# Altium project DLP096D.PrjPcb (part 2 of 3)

## Sheet DLP096D_DMD_Power.SchDoc: DMD Power
size 431 x 279 mm; Date: Not shown in title block; ApprovedBy: Not shown in title block; CheckedBy: Not shown in title block; Author: Not shown in title block; CompanyName: Not shown in title block; DrawnBy: A. Whitehead; Engineer: Not shown in title block; Organization: Not shown in title block; Address1: Not shown in title block; Address2: Not shown in title block; Address3: Not shown in title block; Address4: Not shown in title block; DocumentNumber: 5; Revision: Use project parameter SCH_Rev; SheetNumber: 5; SheetTotal: 10; PageSetup: Record=PageOptions¦CenterHorizontal=True¦CenterVertical=True¦PrintScale=1.00¦XCorrection=1.00¦YCorrection=1.00¦PrintKind=0¦BorderSize=5000000¦LeftOffset=0¦BottomOffset=0¦Orientation=2¦PaperLength=1000¦PaperWidth=1000¦Scale=100¦PaperSource=15¦PrintQuality=600¦MediaType=1¦DitherType=10¦PaperKind=Letter¦PrintScaleMode=1
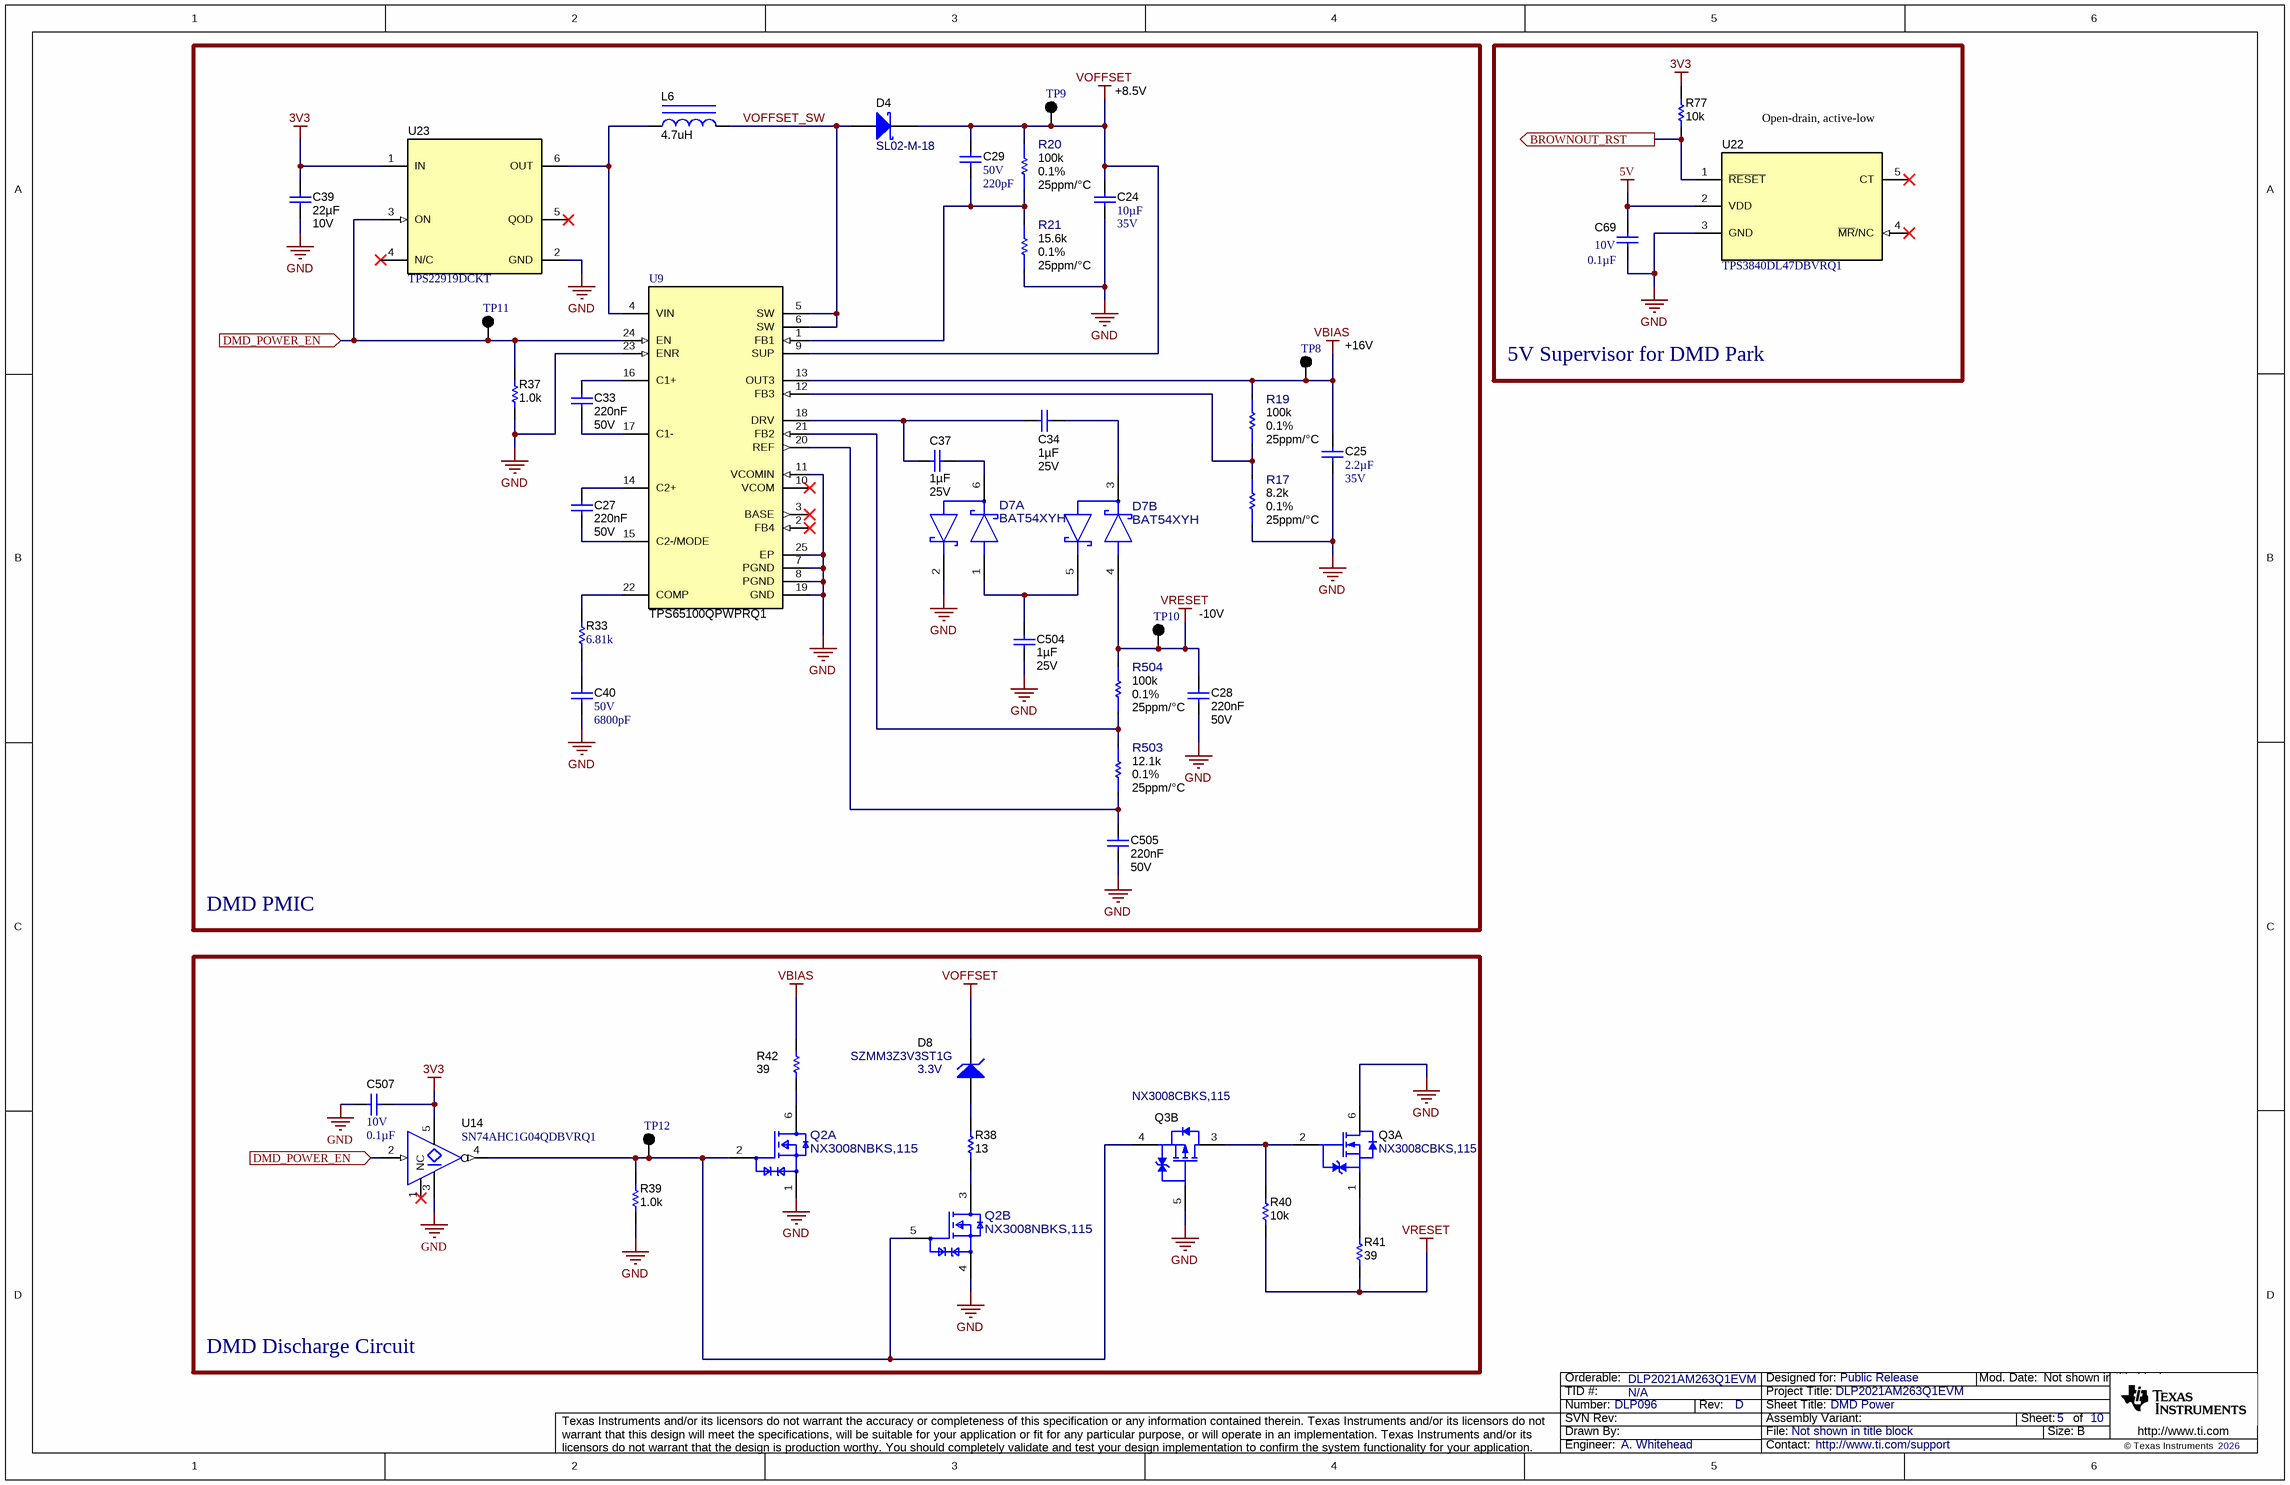
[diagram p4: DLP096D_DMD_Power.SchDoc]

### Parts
C24  Cap_F: 10µF  VDC_V: 35V  [0805_HV]  (hidden comment: C2012X5R1V106K085AC)
C25  Cap_F: 2.2µF  VDC_V: 35V  [0603]  (hidden comment: GRM188R6YA225KA12D)
C27  Cap_F: 220nF  VDC_V: 50V  [0603L]  (hidden comment: GCM188R71E104KA57D)
C28  Cap_F: 220nF  VDC_V: 50V  [0603L]  (hidden comment: GCM188R71E104KA57D)
C29  VDC_V: 50V  ValueDisplayed: 220pF  [0402]  (hidden comment: GRM155R71H221KA01D)
C33  Cap_F: 220nF  VDC_V: 50V  [0603L]  (hidden comment: GCM188R71E104KA57D)
C34  Cap_F: 1µF  VDC_V: 25V  [0603L]  (hidden comment: GCM188R71E105KA64D)
C37  Cap_F: 1µF  VDC_V: 25V  [0603L]  (hidden comment: GCM188R71E105KA64D)
C39  ValueDisplayed: 22µF  VDC_V: 10V  [1206_190L]  (hidden comment: CGA5L1X7S1A226M160AC)
C40  VDC_V: 50V  ValueDisplayed: 6800pF  [0402]  (hidden comment: CGA2B2X7R1H682K050BA)
C69  VDC_V: 10V  ValueDisplayed: 0.1µF  [0402]  (hidden comment: C0402C104K8RACTU)
C504  Cap_F: 1µF  VDC_V: 25V  [0603L]  (hidden comment: GCM188R71E105KA64D)
C505  Cap_F: 220nF  VDC_V: 50V  [0603L]  (hidden comment: CGA3E3X7R1H224K080AB)
C507  VDC_V: 10V  ValueDisplayed: 0.1µF  [0402]  (hidden comment: C0402C104K8RACTU)
D4  SL02-M-18  [DO-219AB]
D7  BAT54XYH  [FP-BAT54XYH_SOT363-IPC_C]  (parts A,B of 2)
D8  SZMM3Z3V3ST1G  value 3.3V  [SOD-323]
L6  ValueDisplayed: 4.7uH  [FDSD0420]  (hidden comment: FDSD0420D-4R7M)
Q2  NX3008NBKS,115  [FP-NX3008NBKS,115_TSSOP6-IPC_C]  (parts A,B of 2)
Q3  NX3008CBKS,115  [SOT-363]  (parts A,B of 2)
R17  Res_ohm: 8.2k  Tolerance_%: 0.1%  TempCo: 25ppm/°C  [FP-ERA-2AEB822X_0402-IPC_C]  (hidden comment: ERA-2AEB822X)
R19  TempCo: 25ppm/°C  Tolerance_%: 0.1%  Res_ohm: 100k  [FP-ERA-2AEB104X_0402-IPC_C]  (hidden comment: ERA-2AEB104X)
R20  TempCo: 25ppm/°C  Tolerance_%: 0.1%  Res_ohm: 100k  [FP-ERA-2AEB104X_0402-IPC_C]  (hidden comment: ERA-2AEB104X)
R21  Res_ohm: 15.6k  Tolerance_%: 0.1%  TempCo: 25ppm/°C  [FP-TNPW040215K6BEED_0402-IPC_C]  (hidden comment: TNPW040215K6BEED)
R33  ValueDisplayed: 6.81k  [0402]  (hidden comment: CRCW04026K81FKED)
R37  ValueDisplayed: 1.0k  [0402L]  (hidden comment: ERJ-2GEJ102X)
R38  ValueDisplayed: 13  [0402L]  (hidden comment: CRCW040213R0JNED)
R39  ValueDisplayed: 1.0k  [0402L]  (hidden comment: ERJ-2GEJ102X)
R40  ValueDisplayed: 10k  [0402L]  (hidden comment: ERJ-2GEJ103X)
R41  ValueDisplayed: 39  [0402L]  (hidden comment: CRCW040239R0JNED)
R42  ValueDisplayed: 39  [0402L]  (hidden comment: CRCW040239R0JNED)
R77  ValueDisplayed: 10k  [0402L]  (hidden comment: ERJ-2GEJ103X)
R503  TempCo: 25ppm/°C  Tolerance_%: 0.1%  Res_ohm: 12.1k  [FP-ERA-2AEB1212X_0402-MFG]  (hidden comment: ERA-2AEB1212X)
R504  TempCo: 25ppm/°C  Tolerance_%: 0.1%  Res_ohm: 100k  [FP-ERA-2AEB104X_0402-MFG]  (hidden comment: ERA-2AEB104X)
TP8  5001  [Keystone5001]  (value not drawn)
TP9  5001  [Keystone5001]  (value not drawn)
TP10  5001  [Keystone5001]  (value not drawn)
TP11  5001  [Keystone5001]  (value not drawn)
TP12  5001  [Keystone5001]  (value not drawn)
U9  TPS65100QPWPRQ1  [PWP0024B_NV_L]
U14  SN74AHC1G04QDBVRQ1  [DBV0005A_N]
U22  TPS3840DL47DBVRQ1  [DBV0005A_N]
U23  TPS22919DCKT  [DCK0006A_N]

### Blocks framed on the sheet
DMD PMIC: C24 C25 C27-C29 C33 C34 C37 C39 C40 C504 C505 D4 D7 L6 R17 R19-R21 R33 R37 R503 R504 TP8-TP11 U9 U23
5V Supervisor for DMD Park: C69 R77 U22
DMD Discharge Circuit: C507 D8 Q2 Q3 R38-R42 TP12 U14

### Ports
BROWNOUT_RST (out), DMD_POWER_EN (in)

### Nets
3V3: C39.2 C507.1 R77.2 U14.5(VCC) U23.1(IN)  [project net VDDS33]
5V: C69.1 U22.2(VDD)
GND: C24.2 C25.1 C28.2 C39.1 C40.1 C69.2 C504.2 C505.2 C507.2 D7.2(cathode_2) Q2.1(S1) Q2.4(S2) Q3.5(G) Q3.6(D) R17.1 R21.1 R37.1 R39.1 U9.7(PGND) U9.8(PGND) U9.11(VCOMIN) U9.19(GND) U9.23(ENR) U9.25(EP) U14.3(GND) U22.3(GND) U23.2(GND)
VBIAS: C25.2 R19.2 R42.2 TP8.1 U9.13(OUT3)
VOFFSET: C24.1 C29.1 D4.1(K) D8.1(K) R20.2 TP9.1 U9.9(SUP)
VRESET: C28.1 D7.4(anode4) R40.1 R41.1 R504.2 TP10.1
BROWNOUT_RST: R77.1 U22.1(~{RESET}) ; port BROWNOUT_RST
DMD_POWER_EN: R37.2 TP11.1 U9.24(EN) U14.2(A) U23.3(ON) ; port DMD_POWER_EN
VOFFSET_SW: D4.2(A) L6.2 U9.5(SW) U9.6(SW)
NetC27_1: C27.1 U9.14(C2+)
NetC27_2: C27.2 U9.15(C2-/MODE)
NetC29_2: C29.2 R20.1 R21.2 U9.1(FB1)
NetC33_1: C33.1 U9.16(C1+)
NetC33_2: C33.2 U9.17(C1-)
NetC34_1: C34.1 D7.3(anode3/cathode4)
NetC34_2: C34.2 C37.1 U9.18(DRV)
NetC37_2: C37.2 D7.6(cathode1/anode2)
NetC40_2: C40.2 R33.1
NetC504_1: C504.1 D7.1(anode_1) D7.5(cathode3)
NetC505_1: C505.1 R503.1 U9.20(REF)
NetD8_2: D8.2(A) R38.2
NetL6_1: L6.1 U9.4(VIN) U23.6(OUT)
NetQ2_2: Q2.2(G1) Q2.5(G2) Q3.4(S) R39.2 TP12.1 U14.4(Y)
NetQ2_3: Q2.3(D2) R38.1
NetQ2_6: Q2.6(D1) R42.1
NetQ3_1: Q3.1(S) R41.2
NetQ3_2: Q3.2(G) Q3.3(D) R40.2
NetR17_2: R17.2 R19.1 U9.12(FB3)
NetR33_2: R33.2 U9.22(COMP)
NetR503_2: R503.2 R504.1 U9.21(FB2)

Not connected (* = marked no-connect by the designer): U9 2(FB4)* 3(BASE)* 10(VCOM)*; U14 1(NC)*; U22 4(~{MR}/NC)* 5(CT)*; U23 4(N/C)* 5(QOD)*

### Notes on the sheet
- +8.5V
- Open-drain, active-low
- (near TP8) +16V
- -10V

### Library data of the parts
C24 = CMP-0007842-2: CAP, CERM, 10 uF, 35 V, +/- 10%, X5R, 0805; Manufacturer: TDK; SizeAreaWB_mm2: 6.75; SizeArea_mm2: 2.5; AEC Qualified: N; AEC Category: Q200; Value: 10uF; TaMax_C: 85°C; SizeZ_mm: 1.45; TaMin_C: -55°C; SizeY_mm: 1.25; U/M: EA; SizeX_mm: 2; Cap_Case: 0805; ESR_ohm: 2.818m; IRMS_A: 3.8868A; Value1: 0.002818 ohm
C25 = CMP-0007356-5: CAP, CERM, 2.2 uF, 35 V, +/- 10%, X5R, 0603; Manufacturer: MuRata; TaMin_C: -55°C; Polarized: N; SizeAreaWB_mm2: 4.68; Value1: Unknown; U/M: EA; Value: 2.2uF; TaMax_C: 85°C; SizeZ_mm: 1; SizeX_mm: 1.6; SizeY_mm: 0.8; SizeArea_mm2: 1.28; AEC Category: Q200
C27 C28 C33 = CMP-0007094-5: CAP, CERM, 0.22 uF, 50 V, +/- 10%, X7R, AEC-Q200 Grade 1, 0603; Manufacturer: TDK; PartNumber: CGA3E3X7R1H224K080AB; TaMin_C: -55°C; ESR_ohm: 0.021699; Polarized: N; SizeAreaWB_mm2: 4.68; Value1: 0.021699 ohm; U/M: EA; Value: 0.22uF; TaMax_C: 125°C; SizeZ_mm: 1; SizeX_mm: 1.6; SizeY_mm: 0.8; Cap_Case: 0603; SizeArea_mm2: 1.28; AEC Qualified: Y; IRMS_A: 1.12496A; AEC Category: Q200
C29 = CMP-0006682-2: CAP, CERM, 220 pF, 50 V, +/- 10%, X7R, 0402; Manufacturer: MuRata; SizeAreaWB_mm2: 3; SizeArea_mm2: 0.5; AEC Category: Q200; Value: 220pF; TaMax_C: 125°C; SizeZ_mm: 0.6; Polarized: N; TaMin_C: -55°C; U/M: EA; SizeX_mm: 1; Value1: Unknown
C34 C37 C504 = CMP-0007139-4: CAP, CERM, 1 uF, 25 V, +/- 10%, X7R, AEC-Q200 Grade 1, 0603; Manufacturer: MuRata; TaMin_C: -55°C; Polarized: N; SizeAreaWB_mm2: 4.68; Value1: Unknown; U/M: EA; Value: 1uF; TaMax_C: 125°C; SizeZ_mm: 1; SizeX_mm: 1.6; SizeY_mm: 0.8; Cap_Case: 0603; SizeArea_mm2: 1.28; AEC Qualified: Y; AEC Category: Q200
C39 = CMP-0088003-2: CAP CER 22UF 10V X7S 1206; Manufacturer: TDK; TempCo: 30ppm/°C; AEC Qualified: Yes; Tolerance_%: 20%; SizeZ_mm: 1.9mm; Value: 22µF
C40 = CMP-0006323-2: CAP, CERM, 6800 pF, 50 V, +/- 10%, X7R, AEC-Q200 Grade 1, 0402; Manufacturer: TDK; TaMin_C: -55°C; ESR_ohm: 0.3916; Polarized: N; SizeAreaWB_mm2: 3; Value1: 0.391597 ohm; U/M: EA; Value: 6800pF; TaMax_C: 125°C; SizeZ_mm: 0.6; SizeX_mm: 1; SizeY_mm: 0.5; AEC Qualified: Y; Cap_F: 6.8nF; IRMS_A: 315.526mA; AEC Category: Q200
C69 C507 = CMP-0078241-1: CAP, CERM, 0.1 µF, 10 V,+/- 10%, X7R, 0402; Manufacturer: Kemet; TaMin_C: -55°C; Polarized: N; SizeAreaWB_mm2: 3; U/M: EA; Value: 0.1uF; TaMax_C: 125°C; SizeZ_mm: 0.6; SizeX_mm: 1; SizeY_mm: 0.5; Cap_F: 100nF; AEC Category: Q200
C505 = CMP-0007094-5: CAP, CERM, 0.22 uF, 50 V, +/- 10%, X7R, AEC-Q200 Grade 1, 0603; Manufacturer: TDK; TaMin_C: -55°C; ESR_ohm: 0.021699; Polarized: N; SizeAreaWB_mm2: 4.68; Value1: 0.021699 ohm; U/M: EA; Value: 0.22uF; TaMax_C: 125°C; SizeZ_mm: 1; SizeX_mm: 1.6; SizeY_mm: 0.8; Cap_Case: 0603; SizeArea_mm2: 1.28; AEC Qualified: Y; IRMS_A: 1.12496A; AEC Category: Q200
D4 = CMP-0028814-3: Diode, Schottky, 20 V, 1.1 A, AEC-Q101, DO-219AB; Manufacturer: Vishay-Semiconductor; Io_A: 1.1A; Green_Lifecycle: Not Set; SizeAreaWB_mm2: 13.16; Vr_V: 20V; Green_REACh: Incomplete; TJmax_C: 125°C; Value: 20V; SizeZ_mm: 1.08; SizeX_mm: 3.7; SizeY_mm: 1.8; Vf_V: 420mV; Value2: 0.42V; SizeArea_mm2: 6.66; AEC Qualified: Y; AEC Category: Q101
D7 = CMP-0086617-1: Diode Array 2 Pair Series Connection Schottky 30V 200mA (DC) Surface Mount 6-TSSOP, SC-88, SOT-363; Manufacturer: Nexperia; SizeZ_mm: 1.1mm; TJmax_C: 125°C; AEC Qualified: Yes
D8 = CMP-0085730-1: Diode, Zener, 3.3 V, 300 mW, AEC-Q101, SOD-323; Manufacturer: ON Semiconductor; RJA_CperW: 416; AEC Qualified: Y; SizeArea_mm2: 3.645; SizeX_mm: 2.7; SizeY_mm: 1.35; SizeZ_mm: 1; AEC Category: Q101; SizeAreaWB_mm2: 8.695; Power_W: 300mW; Value1: 0.3W
L6 = CMP-0058987-1: Inductor, Shielded, 4.7 uH, 2.7 A, 0.083 ohm, AEC-Q200 Grade 1, SMD; Manufacturer: MuRata Toko; PartNumber: FDSD0420D-4R7M=P3; Isat: 2.7A @ 30% inductance drop; Irms: 3.6A @ 40C rise; SizeAreaWB_mm2: 27.04; DCR_ohm: 0.083; Value: 4.7uH; Imax_A: 2.7A; SizeZ_mm: 2; SizeX_mm: 4.2; SizeArea_mm2: 17.64; Ind_H: 4.7µH; AEC Qualified: Y; AEC Grade: 1; AEC Category: Q200
Q2 = CMP-0088579-4: MOSFET 2N-CH 30V 0.35A 6TSSOP; Manufacturer: Nexperia; AEC Qualified: Yes; ChMode: False; Rthja Max: 390K/W; Turn Off Delay Time: 69ns; Rdson45_ohm: 1; Number Of N Channels: 2; Vgs_V: 8V; Pulse Drain Current: 1.4A; TaMin_C: -55°C; TaMax_C: +150°C; Turn On Delay Time: 15ns; AEC Grade: Grade 0; Transconductance: 0.31S; Threshold Vgs Min: 0.6V; Threshold Vgs Max: 1.1V; Input Capacitace At Vds: 34pF @ 15V; SizeZ_mm: 1.1mm; IdsMax_A: 350mA; QgTyp_nC: 0.52nC @ 4.5V; Power_W: 445mW; Typ Forward Diode Voltage: 0.85V; VdsMax_V: 1.2V
Q3 = CMP-0082233-2: MOSFET, 2-CH, N/P-CH, -30 V, -0.2 A, AEC-Q101, SOT-363; Manufacturer: Nexperia; Alternate Manufacturer: None; SizeAreaWB_mm2: 10.24; Value2: 0.55 nC; Rdson45_ohm: 4.1; Value1: 4.1 ohm; SizeX_mm: 2.2; Value: -30V; ChMode: Enhancement; Vgs_V: -8V; SizeArea_mm2: 4.84; AEC Qualified: Y; AEC Category: Q101; ChType: P; QgTyp_nC: 0.55; IdsMax_A: -200mA; SizeZ_mm: 1.1
R17 = CMP-0088626-1: Res Thin Film 0402 8.2K Ohm 0.1% 0.063W(1/16W) ±25ppm/C Pad SMD Automotive T/R; Manufacturer: Panasonic Electronic Components; VDC_V: 50V; AEC Grade: Grade 0; SizeZ_mm: 0.4mm; AEC Qualified: Yes; Power_W: 63mW
R19 R20 R504 = CMP-0088648-1: Res Thin Film 0402 100K Ohm 0.1% 1/16W ±25ppm/°C Molded SMD SMD Punched Carrier T/R; Manufacturer: Panasonic; Category 7542B8484461Ae85: Passive Components; VDC_V: 50V; Category Cd01000Bfc2916C6: Single Components; Power_W: 63mW; Category 5A00970A6D5C81C7: Uncategorized; AEC Qualified: Yes; SizeZ_mm: 0.4mm; AEC Grade: Grade 0; Category 5C6A91606D4187Ad: Resistors
R21 = CMP-0088630-1: Res Thin Film 0402 15.6K Ohm 0.1% 1/10W ±25ppm/°C Molded SMD Paper T/R; Manufacturer: Vishay; Power_W: 100mW; SizeZ_mm: 0.4mm; AEC Qualified: Yes; AEC Grade: Grade 0; VDC_V: 50V
R33 = CMP-0026517-2: RES, 6.81 k, 1%, 0.063 W, AEC-Q200 Grade 0, 0402; Manufacturer: Vishay-Dale; Power_W: 63mW; TempCo: 100 ppm/C; Value_Code: 6k81; Value: 6.81k; EIA_Code: E96; SizeX_mm: 1; SizeY_mm: 0.5; SizeZ_mm: 0.6; Value2: 0.063W; AEC Qualified: Y; VDC_V: 50V; AEC Category: Q200; AEC Grade: 0
R37 R39 = CMP-0078193-1: RES, 1.0 k, 5%, 0.1 W, AEC-Q200 Grade 0, 0402; Manufacturer: Panasonic; Value_Code: 1k00; SizeArea_mm2: 0.5; AEC Qualified: Y; AEC Category: Q200; Res_ohm: 1k; Value: 1.0k; SizeZ_mm: 0.6; Green_REACh: Passed; EIA_Code: E24; TempCo: 200 ppm/C; AEC Grade: 0; Power_W: 100mW; VDC_V: 50V; Value2: 0.1W; Green_Lifecycle: Active; U/M: EA; SizeX_mm: 1
R38 = CMP-0026839-3: RES, 13, 5%, 0.063 W, AEC-Q200 Grade 0, 0402; Manufacturer: Vishay-Dale; Power_W: 63mW; TempCo: 200 ppm/C; Value_Code: 13R0; Value: 13; EIA_Code: E24; SizeX_mm: 1; SizeY_mm: 0.5; SizeZ_mm: 0.6; Value2: 0.063W; AEC Qualified: Y; VDC_V: 50V; AEC Category: Q200; AEC Grade: 0
R40 R77 = CMP-0026994-4: RES, 10 k, 5%, 0.1 W, AEC-Q200 Grade 0, 0402; Manufacturer: Panasonic; Power_W: 100mW; TempCo: 200 ppm/C; Value_Code: 10k0; U/M: EA; Value: 10k; EIA_Code: E24; SizeX_mm: 1; SizeY_mm: 0.5; SizeZ_mm: 0.6; Value2: 0.1W; AEC Qualified: Y; VDC_V: 50V; AEC Grade: 0; AEC Category: Q200
R41 R42 = CMP-0026916-3: RES, 39, 5%, 0.063 W, AEC-Q200 Grade 0, 0402; Manufacturer: Vishay-Dale; Power_W: 63mW; TempCo: 200 ppm/C; Value_Code: 39R0; Value: 39; EIA_Code: E24; SizeX_mm: 1; SizeY_mm: 0.5; SizeZ_mm: 0.6; Value2: 0.063W; AEC Qualified: Y; VDC_V: 50V; AEC Category: Q200; AEC Grade: 0
R503 = CMP-0088636-1: RES SMD 12.1KOHM 0.1% 1/16W 0402; Manufacturer: Panasonic Electronic Components; SizeZ_mm: 0.4mm; AEC Qualified: Yes; AEC Grade: Grade 0; Power_W: 63mW; VDC_V: 50V
TP8 TP10-TP12 = CMP-0055138-1: Test Point, Miniature, Black, TH; Manufacturer: Keystone; CNHeader: FALSE; Green_Lifecycle: Active; Green_REACh: Passed; ContactFinish: Silver; CT: TRUE
TP9 = CMP-0055138-2: Test Point, Miniature, Black, TH; Manufacturer: Keystone Electronics; CNHeader: FALSE; Green_Lifecycle: Active; Green_REACh: Passed; ContactFinish: Silver; CT: TRUE
U9 = CMP-0034937-2: Dimmable Quasi-Resonant LED Lighting Controller, 9 to 21.5 V, -40 to 140 degC, 16-pin SOP (PW16), Green (RoHS & no Sb/Br); Manufacturer: Texas Instruments; SubFamily: LCD/OLED Display Bias Solutions; Rating: Automotive; Topology: Boost, Inverting Buck/Boost; Vin(Max)(V): 5.8; Vin(Min)(V): 2.7; Iout(Max)(A): 0.35; Iq(Typ)(mA): 0.75; Synchronous Rectification: TRUE; Switching Frequency(Typ)(kHz): 1600
U14 = CMP-0051688-3: Automotive Catalog Single Inverter Gate, DBV0005A (SOT-23-5); Manufacturer: Texas Instruments; Generic Part Number: SN74AHC1G04-Q1; Output Type: CMOS; tpd @ Nom Voltage(Max)(ns): 10.6,7.5; Bits(#): 1; Schmitt Trigger: No; VCC(Max)(V): 5.5; CompType: IC; Voltage(Nom)(V): 3.3,5; SizeAreaWB_mm2: 14.82; SizeX_mm: 2.8; ICC @ Nom Voltage(Max)(mA): 0.01; F @ Nom Voltage(Max)(Mhz): 75; SizeY_mm: 2.9; Logic: Inverting; AEC Category: Q200; Output Drive (IOL/IOH)(Max)(mA): 50/-50; SizeArea_mm2: 8.12; AEC Qualified: Y; SizeZ_mm: 1.45; VCC(Min)(V): 2
U22 = CMP-0861099-1: Automotive high-input voltage supervisor with manual reset and programmable-reset time delay, DBV0005A (SOT-23-5); Manufacturer: Texas Instruments; SizeArea_mm2: 8.12; AEC Qualified: Y; AEC Category: Q200; SizeX_mm: 2.8; SizeY_mm: 2.9; CompType: IC; SizeAreaWB_mm2: 14.82; SizeZ_mm: 1.45
U23 = CMP-0081107-1: 5.5-V, 1.5-A, 100-mohm Load Switch with Output Discharge, DCK0006A (SOT-SC70-6); Alternate PartNumber: TPS22919DCKR; Alternate Manufacturer: Texas Instruments; SizeAreaWB_mm2: 9.3; SizeZ_mm: 1.1; SizeX_mm: 2.1; SizeY_mm: 2; SizeArea_mm2: 4.2; CompType: IC; AEC Qualified: N; AEC Category: Q200

## Sheet DLP096D_DMD_Interface.SchDoc: DMD Interface
size 431 x 279 mm; Date: Not shown in title block; ApprovedBy: Not shown in title block; CheckedBy: Not shown in title block; Author: Not shown in title block; CompanyName: Not shown in title block; DrawnBy: A. Whitehead; Engineer: Not shown in title block; Organization: Not shown in title block; Address1: Not shown in title block; Address2: Not shown in title block; Address3: Not shown in title block; Address4: Not shown in title block; DocumentNumber: 6; Revision: Use project parameter SCH_Rev; SheetNumber: 6; SheetTotal: 10; PageSetup: Record=PageOptions¦CenterHorizontal=True¦CenterVertical=True¦PrintScale=1.00¦XCorrection=1.00¦YCorrection=1.00¦PrintKind=0¦BorderSize=5000000¦LeftOffset=0¦BottomOffset=0¦Orientation=2¦PaperLength=1000¦PaperWidth=1000¦Scale=100¦PaperSource=15¦PrintQuality=600¦MediaType=1¦DitherType=10¦PaperKind=Letter¦PrintScaleMode=1
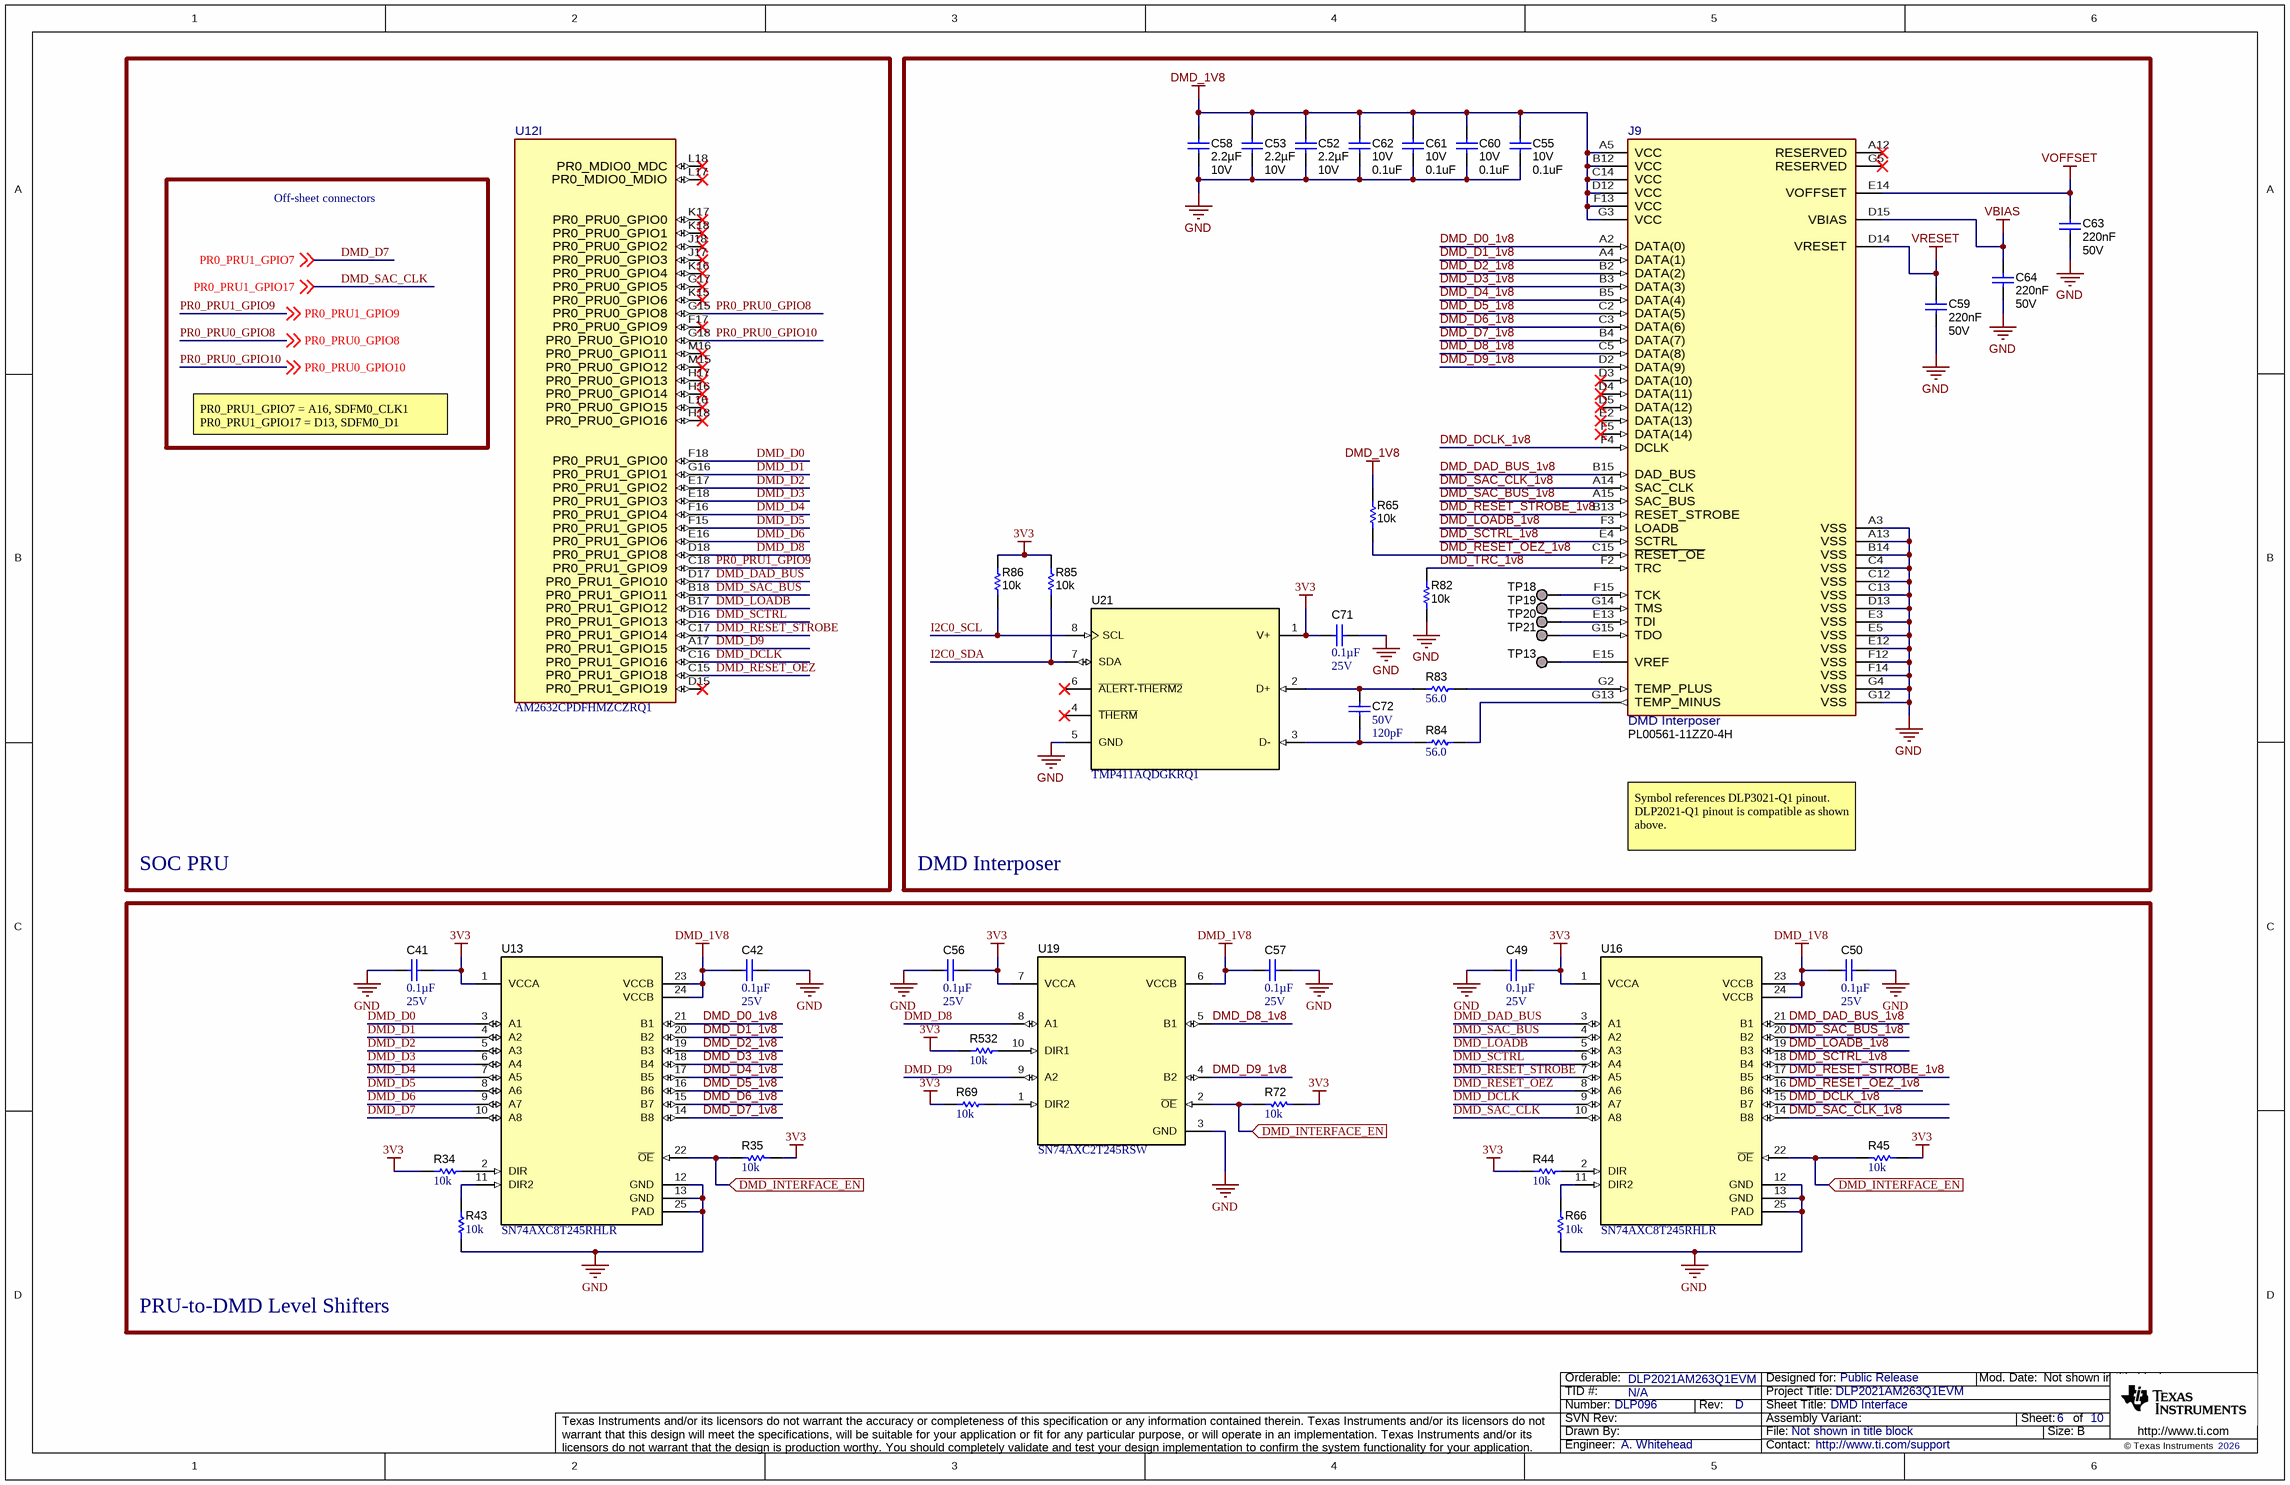
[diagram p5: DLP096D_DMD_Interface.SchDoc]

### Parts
C41  ValueDisplayed: 0.1µF  VDC_V: 25V  [0402]  (hidden comment: GCM155L81E104KE02D)
C42  ValueDisplayed: 0.1µF  VDC_V: 25V  [0402]  (hidden comment: GCM155L81E104KE02D)
C49  ValueDisplayed: 0.1µF  VDC_V: 25V  [0402]  (hidden comment: GCM155L81E104KE02D)
C50  ValueDisplayed: 0.1µF  VDC_V: 25V  [0402]  (hidden comment: GCM155L81E104KE02D)
C52  Cap_F: 2.2µF  VDC_V: 10V  [0603L]  (hidden comment: GRM188R71A225KE15J)
C53  Cap_F: 2.2µF  VDC_V: 10V  [0603L]  (hidden comment: GRM188R71A225KE15J)
C55  VDC_V: 10V  ValueDisplayed: 0.1uF  [0402L]  (hidden comment: GCM155R71A104KA55D)
C56  ValueDisplayed: 0.1µF  VDC_V: 25V  [0402]  (hidden comment: GCM155L81E104KE02D)
C57  ValueDisplayed: 0.1µF  VDC_V: 25V  [0402]  (hidden comment: GCM155L81E104KE02D)
C58  Cap_F: 2.2µF  VDC_V: 10V  [0603L]  (hidden comment: GRM188R71A225KE15J)
C59  Cap_F: 220nF  VDC_V: 50V  [0603L]  (hidden comment: GCM188R71E104KA57D)
C60  VDC_V: 10V  ValueDisplayed: 0.1uF  [0402L]  (hidden comment: GCM155R71A104KA55D)
C61  VDC_V: 10V  ValueDisplayed: 0.1uF  [0402L]  (hidden comment: GCM155R71A104KA55D)
C62  VDC_V: 10V  ValueDisplayed: 0.1uF  [0402L]  (hidden comment: GCM155R71A104KA55D)
C63  Cap_F: 220nF  VDC_V: 50V  [0603L]  (hidden comment: GCM188R71E104KA57D)
C64  Cap_F: 220nF  VDC_V: 50V  [0603L]  (hidden comment: GCM188R71E104KA57D)
C71  ValueDisplayed: 0.1µF  VDC_V: 25V  [0402]  (hidden comment: GCM155L81E104KE02D)
C72  VDC_V: 50V  ValueDisplayed: 120pF  [0402]  (hidden comment: GRM1555C1H121FA01D)
J9  DMD Interposer  PartNumber: PL00561-11ZZ0-4H  [FP-2516672_SMD_CONN_LGA-56-MFG]
R34  ValueDisplayed: 10k  [0603]  (hidden comment: CRCW060310K0JNEA)
R35  ValueDisplayed: 10k  [0603]  (hidden comment: CRCW060310K0JNEA)
R43  ValueDisplayed: 10k  [0603]  (hidden comment: CRCW060310K0JNEA)
R44  ValueDisplayed: 10k  [0603]  (hidden comment: CRCW060310K0JNEA)
R45  ValueDisplayed: 10k  [0603]  (hidden comment: CRCW060310K0JNEA)
R65  ValueDisplayed: 10k  [0201]  (hidden comment: RC0201JR-0710KL)
R66  ValueDisplayed: 10k  [0603]  (hidden comment: CRCW060310K0JNEA)
R69  ValueDisplayed: 10k  [0603]  (hidden comment: CRCW060310K0JNEA)
R72  ValueDisplayed: 10k  [0603]  (hidden comment: CRCW060310K0JNEA)
R82  ValueDisplayed: 10k  [0201]  (hidden comment: RC0201JR-0710KL)
R83  ValueDisplayed: 56.0  [0603]  (hidden comment: RC0603FR-0756RL)
R84  ValueDisplayed: 56.0  [0603]  (hidden comment: RC0603FR-0756RL)
R85  ValueDisplayed: 10k  [0201]  (hidden comment: RC0201JR-0710KL)
R86  ValueDisplayed: 10k  [0201]  (hidden comment: RC0201JR-0710KL)
R532  ValueDisplayed: 10k  [0603]  (hidden comment: CRCW060310K0JNEA)
TP13  TP_H0.45P0.75  [TP_H045P075]  (value not drawn)  (no BOM)
TP18  TP_H0.45P0.75  [TP_H045P075]  (value not drawn)  (no BOM)
TP19  TP_H0.45P0.75  [TP_H045P075]  (value not drawn)  (no BOM)
TP20  TP_H0.45P0.75  [TP_H045P075]  (value not drawn)  (no BOM)
TP21  TP_H0.45P0.75  [TP_H045P075]  (value not drawn)  (no BOM)
U12  AM2632CPDFHMZCZRQ1  [ZCZ0324A-MFG]  (part I of 13)
U13  SN74AXC8T245RHLR  [RHL0024A]
U16  SN74AXC8T245RHLR  [RHL0024A]
U19  SN74AXC2T245RSW  [RSW0010A]
U21  TMP411AQDGKRQ1  [DGK0008A_N]

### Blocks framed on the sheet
SOC PRU: U12
DMD Interposer: C52 C53 C55 C58-C64 C71 C72 J9 R65 R82-R86 TP13 TP18-TP21 U21
PRU-to-DMD Level Shifters: C41 C42 C49 C50 C56 C57 R34 R35 R43-R45 R66 R69 R72 R532 U13 U16 U19

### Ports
DMD_INTERFACE_EN (in)

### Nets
3V3: C41.1 C49.1 C56.1 C71.1 R34.1 R35.1 R44.1 R45.1 R69.2 R72.1 R85.2 R86.2 R532.1 U13.1(VCCA) U16.1(VCCA) U19.7(VCCA) U21.1(V+)  [project net VDDS33]
DMD_1V8: C42.2 C50.2 C52.1 C53.1 C55.1 C57.2 C58.1 C60.1 C61.1 C62.1 J9.A5(VCC) J9.B12(VCC) J9.C14(VCC) J9.D12(VCC) J9.F13(VCC) J9.G3(VCC) R65.2 U13.23(VCCB) U13.24(VCCB) U16.23(VCCB) U16.24(VCCB) U19.6(VCCB)
GND: C41.2 C42.1 C49.2 C50.1 C52.2 C53.2 C55.2 C56.2 C57.1 C58.2 C59.2 C60.2 C61.2 C62.2 C63.2 C64.2 C71.2 J9.A3(VSS) J9.A13(VSS) J9.B14(VSS) J9.C4(VSS) J9.C12(VSS) J9.C13(VSS) J9.D13(VSS) J9.E3(VSS) J9.E5(VSS) J9.E12(VSS) J9.F12(VSS) J9.F14(VSS) J9.G4(VSS) J9.G12(VSS) R43.1 R66.1 R82.1 U13.12(GND) U13.13(GND) U13.25(PAD) U16.12(GND) U16.13(GND) U16.25(PAD) U19.3(GND) U21.5(GND)
VBIAS: C64.1 J9.D15(VBIAS)
VOFFSET: C63.1 J9.E14(VOFFSET)
VRESET: C59.1 J9.D14(VRESET)
DMD_D0: U12.F18(PR0_PRU1_GPIO0) U13.3(A1)
DMD_D0_1v8: J9.A2(DATA(0)) U13.21(B1)
DMD_D1: U12.G16(PR0_PRU1_GPIO1) U13.4(A2)
DMD_D1_1v8: J9.A4(DATA(1)) U13.20(B2)
DMD_D2: U12.E17(PR0_PRU1_GPIO2) U13.5(A3)
DMD_D2_1v8: J9.B2(DATA(2)) U13.19(B3)
DMD_D3: U12.E18(PR0_PRU1_GPIO3) U13.6(A4)
DMD_D3_1v8: J9.B3(DATA(3)) U13.18(B4)
DMD_D4: U12.F16(PR0_PRU1_GPIO4) U13.7(A5)
DMD_D4_1v8: J9.B5(DATA(4)) U13.17(B5)
DMD_D5: U12.F15(PR0_PRU1_GPIO5) U13.8(A6)
DMD_D5_1v8: J9.C2(DATA(5)) U13.16(B6)
DMD_D6: U12.E16(PR0_PRU1_GPIO6) U13.9(A7)
DMD_D6_1v8: J9.C3(DATA(6)) U13.15(B7)
DMD_D7: U13.10(A8) ; off-sheet PR0_PRU1_GPIO7  [also labelled PR0_PRU1_GPIO7]
DMD_D7_1v8: J9.B4(DATA(7)) U13.14(B8)
DMD_D8: U12.D18(PR0_PRU1_GPIO8) U19.8(A1)
DMD_D8_1v8: J9.C5(DATA(8)) U19.5(B1)
DMD_D9: U12.A17(PR0_PRU1_GPIO15) U19.9(A2)
DMD_D9_1v8: J9.D2(DATA(9)) U19.4(B2)
DMD_DAD_BUS: U12.D17(PR0_PRU1_GPIO10) U16.3(A1)
DMD_DAD_BUS_1v8: J9.B15(DAD_BUS) U16.21(B1)
DMD_DCLK: U12.C16(PR0_PRU1_GPIO16) U16.9(A7)
DMD_DCLK_1v8: J9.F4(DCLK) U16.15(B7)
DMD_INTERFACE_EN: R35.2 R45.2 R72.2 U13.22(~{OE}) U16.22(~{OE}) U19.2(~{OE}) ; port DMD_INTERFACE_EN
DMD_LOADB: U12.B17(PR0_PRU1_GPIO12) U16.5(A3)
DMD_LOADB_1v8: J9.F3(LOADB) U16.19(B3)
DMD_RESET_OEZ: U12.C15(PR0_PRU1_GPIO18) U16.8(A6)
DMD_RESET_OEZ_1v8: J9.C15(~{RESET_OE}) R65.1 U16.16(B6)
DMD_RESET_STROBE: U12.C17(PR0_PRU1_GPIO14) U16.7(A5)
DMD_RESET_STROBE_1v8: J9.B13(RESET_STROBE) U16.17(B5)
DMD_SAC_BUS: U12.B18(PR0_PRU1_GPIO11) U16.4(A2)
DMD_SAC_BUS_1v8: J9.A15(SAC_BUS) U16.20(B2)
DMD_SAC_CLK: U16.10(A8) ; off-sheet PR0_PRU1_GPIO17  [also labelled PR0_PRU1_GPIO17]
DMD_SAC_CLK_1v8: J9.A14(SAC_CLK) U16.14(B8)
DMD_SCTRL: U12.D16(PR0_PRU1_GPIO13) U16.6(A4)
DMD_SCTRL_1v8: J9.E4(SCTRL) U16.18(B4)
DMD_TRC_1v8: J9.F2(TRC) R82.2
I2C0_SCL: R86.1 U21.8(SCL)
I2C0_SDA: R85.1 U21.7(SDA)
PR0_PRU0_GPIO8: U12.G15(PR0_PRU0_GPIO8) ; off-sheet PR0_PRU0_GPIO8  [project net GPMC_WPn]
PR0_PRU0_GPIO10: U12.G18(PR0_PRU0_GPIO10) ; off-sheet PR0_PRU0_GPIO10  [project net GPMC_WAIT0]
PR0_PRU1_GPIO9: U12.C18(PR0_PRU1_GPIO9) ; off-sheet PR0_PRU1_GPIO9  [project net GPMC_BE0n_CLE]
NetC72_1: C72.1 R83.1 U21.2(D+)
NetC72_2: C72.2 R84.1 U21.3(D-)
NetJ9_E13: J9.E13(TDI) TP20.1
NetJ9_E15: J9.E15(VREF) TP13.1
NetJ9_F15: J9.F15(TCK) TP18.1
NetJ9_G2: J9.G2(TEMP_PLUS) R83.2
NetJ9_G13: J9.G13(TEMP_MINUS) R84.2
NetJ9_G14: J9.G14(TMS) TP19.1
NetJ9_G15: J9.G15(TDO) TP21.1
NetR34_2: R34.2 U13.2(DIR)
NetR43_2: R43.2 U13.11(DIR2)
NetR44_2: R44.2 U16.2(DIR)
NetR66_2: R66.2 U16.11(DIR2)
NetR69_1: R69.1 U19.1(DIR2)
NetR532_2: R532.2 U19.10(DIR1)

Not connected (* = marked no-connect by the designer): J9 A12(RESERVED)* D3(DATA(10))* D4(DATA(11))* D5(DATA(12))* E2(DATA(13))* F5(DATA(14))* G5(RESERVED)*; U12 D15(PR0_PRU1_GPIO19)* F17(PR0_PRU0_GPIO9)* G17(PR0_PRU0_GPIO5)* H16(PR0_PRU0_GPIO14)* H17(PR0_PRU0_GPIO13)* H18(PR0_PRU0_GPIO16)* J17(PR0_PRU0_GPIO3)* J18(PR0_PRU0_GPIO2)* K15(PR0_PRU0_GPIO6)* K16(PR0_PRU0_GPIO4)* K17(PR0_PRU0_GPIO0)* K18(PR0_PRU0_GPIO1)* L16(PR0_PRU0_GPIO15)* L17(PR0_MDIO0_MDIO)* L18(PR0_MDIO0_MDC)* M15(PR0_PRU0_GPIO12)* M16(PR0_PRU0_GPIO11)*; U21 4(~{THERM})* 6(~{ALERT}-~{THERM2})*

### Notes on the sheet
- Off-sheet connectors
- PR0_PRU1_GPIO7 = A16, SDFM0_CLK1
  PR0_PRU1_GPIO17 = D13, SDFM0_D1
- Symbol references DLP3021-Q1 pinout. DLP2021-Q1 pinout is compatible as shown above.

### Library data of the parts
C41 C42 C49 C50 C56 C57 C71 = CMP-0861000-1: CAP, CERM, 0.1 µF, 25 V,+/- 10%, X8L, AEC-Q200 Grade 0, 0402; Manufacturer: MuRata; U/M: EA; Polarized: N; Cap_F: 100nF; SizeZ_mm: 0.6; SizeY_mm: 0.5; Value: 0.1uF; SizeX_mm: 1; AEC Qualified: Y; AEC Grade: 0; SizeAreaWB_mm2: 3; AEC Category: Q200; TaMin_C: -55°C; TaMax_C: 150°C
C52 C53 C58 = CMP-0084284-1: CAP, CERM, 2.2 µF, 10 V,+/- 10%, X7R, AEC-Q200 Grade 1, 0603; Manufacturer: MuRata; SizeAreaWB_mm2: 4.68; Polarized: N; AEC Qualified: Y; SizeX_mm: 1.6; SizeZ_mm: 1; SizeY_mm: 0.8; U/M: EA; TaMin_C: -55°C; Value: 2.2uF; Cap_Case: 0603; AEC Category: Q200; TaMax_C: 125°C; SizeArea_mm2: 1.28
C55 C60-C62 = CMP-0006350-2: CAP, CERM, 0.1 uF, 10 V, +/- 10%, X7R, AEC-Q200 Grade 1, 0402; Manufacturer: MuRata; TaMin_C: -55°C; Polarized: N; SizeAreaWB_mm2: 3; Value1: Unknown; U/M: EA; Value: 0.1uF; TaMax_C: 125°C; SizeZ_mm: 0.6; SizeX_mm: 1; SizeY_mm: 0.5; Cap_Case: 0402; AEC Qualified: Y; Cap_F: 100nF; AEC Category: Q200
C59 C63 C64 = CMP-0007094-5: as C27 on sheet DLP096D_DMD_Power
C72 = CMP-0006416-2: CAP, CERM, 120 pF, 50 V, +/- 1%, C0G/NP0, 0402; Manufacturer: MuRata; TaMin_C: -55°C; Polarized: N; SizeAreaWB_mm2: 3; Value1: Unknown; U/M: EA; Value: 120pF; TaMax_C: 125°C; SizeZ_mm: 0.6; SizeX_mm: 1; SizeY_mm: 0.5; AEC Category: Q200
J9 = CMP-0087816-2: NTERPOSER, 56 CONTACT, HOLE DATUM; Alternate Manufacturer: Neoconix; Alternate PartNumber: BDX0056DMMSXAU00; Manufacturer: Foxconn Interconnect Technology; DUT-Pitch_mm: 1mm; SizeZ_mm: 1.4mm
R34 R35 R43-R45 R66 R69 R72 R532 = CMP-0025701-1: RES, 10 k, 5%, 0.1 W, 0603; Manufacturer: Vishay-Dale; Power_W: 100mW; TempCo: 200 ppm/C; Value_Code: 10k0; U/M: EA; Value: 10k; EIA_Code: E24; SizeX_mm: 1.6; SizeY_mm: 0.8; SizeZ_mm: 1; Value2: 0.1W; SizeArea_mm2: 1.28; VDC_V: 75V; AEC Category: Q200
R65 R82 R85 R86 = CMP-0027019-1: RES, 10 k, 5%, 0.05 W, 0201; Manufacturer: Yageo America; Power_W: 50mW; TempCo: 200 ppm/C; Value_Code: 10k0; U/M: EA; Value: 10k; EIA_Code: E24; SizeX_mm: 0.6; SizeY_mm: 0.3; SizeZ_mm: 0.26; Value2: 0.05W; SizeArea_mm2: 0.18; AEC Qualified: N; VDC_V: 25V; AEC Category: Q200
R83 R84 = CMP-0023188-5: RES, 56.0, 1%, 0.1 W, 0603; Manufacturer: Yageo; Power_W: 100mW; TempCo: 100 ppm/C; Value_Code: 56R0; Value: 56.0; Res_ohm: 56; SizeX_mm: 1.6; SizeY_mm: 0.8; SizeZ_mm: 1; Value2: 0.1W; SizeArea_mm2: 1.28; AEC Qualified: N; VDC_V: 75V; AEC Category: Q200; SizeAreaWB_mm2: 4.68
TP13 TP18-TP21 = CMP-0003719-1: Testpoint; Manufacturer: Texas Instruments; CompType: Pad
U12 = CMP-0093674-1: Sitara™ Microcontrollers; Manufacturer: Texas Instruments; Min Supply Voltage: 1.14V; Number Of Adc Channels: 30; AEC Qualified: No; TJmax_C: +105°C; Memory Type: SRAM; Standoff Height: 0.35mm; Core Architecture: ARM Cortex-R5F; Number Of I2C Channels: 4; Number Of Pwm Channels: 24; Number Of Spi Channels: 5; Number Of Cores: 2; Frequency_Fixed: 400MHz; Nominal Supply Current: 200-2500mA; Ram Size: 2MBytes; Number Of Ethernet Channels: 1; Interface: I2C,SPI,UART,CAN,LIN,Ethernet,Other; Data Bus Width: 64bits; SizeZ_mm: 1.4mm; Number Of Uart Channels: 6; Number Of I/Os: 140; Max Supply Voltage: 3.465V
U13 U16 = CMP-0065229-3: Asynchronous Communication Between Data Buses, RHL0024A (VQFN-24); Manufacturer: Texas Instruments; Alternate PartNumber: SN74AXC8T245RHLT; SizeX_mm: 3.5; SizeY_mm: 5.5; CompType: IC; SizeZ_mm: 1.0; SizeArea_mm2: 19.25; SizeAreaWB_mm2: 41.25; AEC Category: Q200; AEC Qualified: N
U19 = CMP-0860382-1: SN74AXC2T245RSW, RSW0010A (UQFN-10); Alternate Manufacturer: Texas Instruments; SizeZ_mm: 0.55; AEC Qualified: N; SizeArea_mm2: 2.52; CompType: IC; SizeX_mm: 1.4; SizeY_mm: 1.8; AEC Category: Q200; SizeAreaWB_mm2: 6.72
U21 = CMP-0860146-1: Automotive Grade, Remote and Local Temperature Sensor with N-Factor and Series-R Correction, DGK0008A (VSSOP-8); Alternate Manufacturer: Texas Instruments; SizeAreaWB_mm2: 23.6; SizeArea_mm2: 14.7; SizeX_mm: 4.9; AEC Category: Q200; SizeZ_mm: 1.1; CompType: IC; AEC Qualified: Y; SizeY_mm: 3

## Sheet DLP096D_SoC_Memory.SchDoc: SoC Memory
size 431 x 279 mm; Date: Not shown in title block; ApprovedBy: Not shown in title block; CheckedBy: Not shown in title block; Author: Not shown in title block; CompanyName: Not shown in title block; DrawnBy: A. Whitehead; Engineer: Not shown in title block; Organization: Not shown in title block; Address1: Not shown in title block; Address2: Not shown in title block; Address3: Not shown in title block; Address4: Not shown in title block; DocumentNumber: 7; Revision: Use project parameter SCH_Rev; SheetNumber: 7; SheetTotal: 10; PageSetup: Record=PageOptions¦CenterHorizontal=True¦CenterVertical=True¦PrintScale=1.00¦XCorrection=1.00¦YCorrection=1.00¦PrintKind=0¦BorderSize=5000000¦LeftOffset=0¦BottomOffset=0¦Orientation=2¦PaperLength=1000¦PaperWidth=1000¦Scale=100¦PaperSource=15¦PrintQuality=600¦MediaType=1¦DitherType=10¦PaperKind=Letter¦PrintScaleMode=1
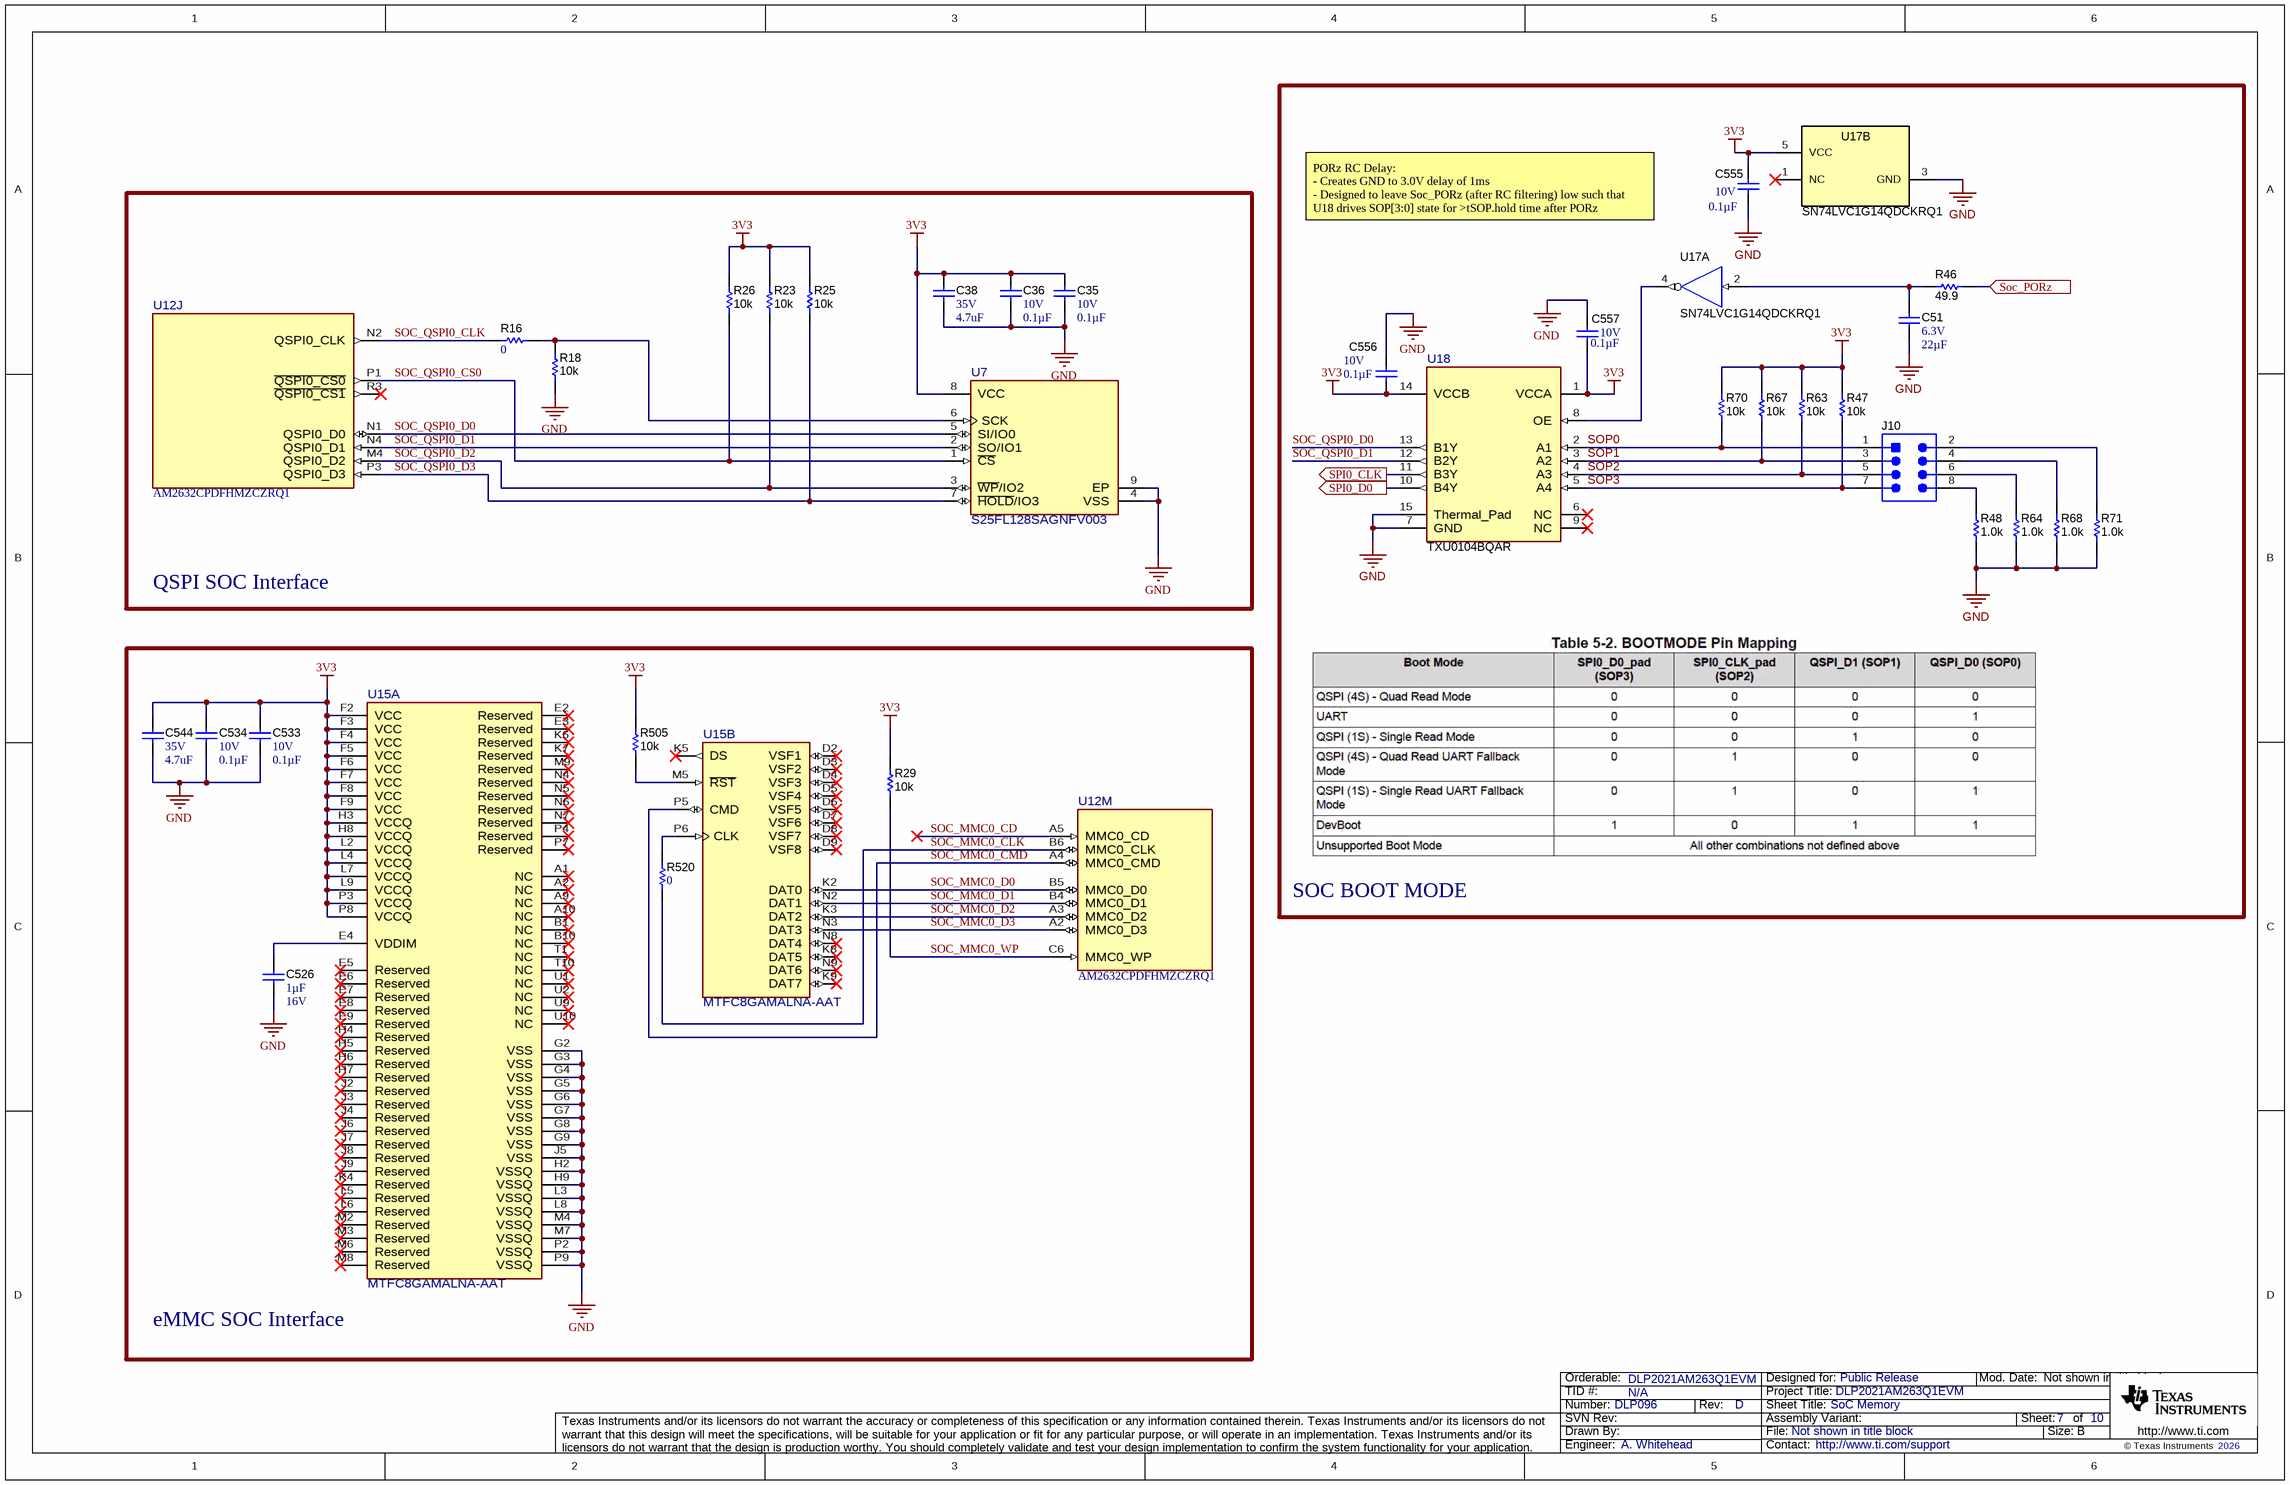
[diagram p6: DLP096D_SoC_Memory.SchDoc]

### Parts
C35  VDC_V: 10V  ValueDisplayed: 0.1µF  [0201_033]  (hidden comment: GRM033R61A104KE84D)
C36  VDC_V: 10V  ValueDisplayed: 0.1µF  [0201_033]  (hidden comment: GRM033R61A104KE84D)
C38  VDC_V: 35V  ValueDisplayed: 4.7uF  [0603]  (hidden comment: C1608X5R1V475K080AC)
C51  VDC_V: 6.3V  ValueDisplayed: 22µF  [0603]  (hidden comment: GRM186R60J226ME15D)
C526  Cap_F: 1µF  VDC_V: 16V  [0603]  (hidden comment: CGA3E1X7R1C105K080AC)
C533  VDC_V: 10V  ValueDisplayed: 0.1µF  [0201_033]  (hidden comment: GRM033R61A104KE84D)
C534  VDC_V: 10V  ValueDisplayed: 0.1µF  [0201_033]  (hidden comment: GRM033R61A104KE84D)
C544  VDC_V: 35V  ValueDisplayed: 4.7uF  [0603]  (hidden comment: C1608X5R1V475K080AC)
C555  VDC_V: 10V  ValueDisplayed: 0.1µF  [0402]  (hidden comment: C0402C104K8RACTU)
C556  VDC_V: 10V  ValueDisplayed: 0.1µF  [0402]  (hidden comment: C0402C104K8RACTU)
C557  VDC_V: 10V  ValueDisplayed: 0.1µF  [0402]  (hidden comment: C0402C104K8RACTU)
J10  TSM-104-01-L-DV  [Samtec_TSM-104-01-x-DV]  (value not drawn)
R16  ValueDisplayed: 0  [0402]  (hidden comment: MCR01MZPJ000)
R18  ValueDisplayed: 10k  [0201]  (hidden comment: RC0201JR-0710KL)
R23  ValueDisplayed: 10k  [0201]  (hidden comment: RC0201JR-0710KL)
R25  ValueDisplayed: 10k  [0201]  (hidden comment: RC0201JR-0710KL)
R26  ValueDisplayed: 10k  [0201]  (hidden comment: RC0201JR-0710KL)
R29  ValueDisplayed: 10k  [0201]  (hidden comment: RC0201JR-0710KL)
R46  ValueDisplayed: 49.9  [0603]  (hidden comment: ERJ-3EKF49R9V)
R47  ValueDisplayed: 10k  [0201]  (hidden comment: RC0201JR-0710KL)
R48  ValueDisplayed: 1.0k  [0402L]  (hidden comment: ERJ-2GEJ102X)
R63  ValueDisplayed: 10k  [0201]  (hidden comment: RC0201JR-0710KL)
R64  ValueDisplayed: 1.0k  [0402L]  (hidden comment: ERJ-2GEJ102X)
R67  ValueDisplayed: 10k  [0201]  (hidden comment: RC0201JR-0710KL)
R68  ValueDisplayed: 1.0k  [0402L]  (hidden comment: ERJ-2GEJ102X)
R70  ValueDisplayed: 10k  [0201]  (hidden comment: RC0201JR-0710KL)
R71  ValueDisplayed: 1.0k  [0402L]  (hidden comment: ERJ-2GEJ102X)
R505  ValueDisplayed: 10k  [0201]  (hidden comment: RC0201JR-0710KL)
R520  ValueDisplayed: 0  [0402]  (hidden comment: MCR01MZPJ000)
U7  S25FL128SAGNFV003  [FP-S25FL128SAGNFI000_WSON8-MFG]
U12  PartNumber: AM2632CPDFHMZCZRQ1  [ZCZ0324A-MFG]  (hidden comment: XAM2634AOLFGMZCZQ)  (parts J,M of 13)
U15  MTFC8GAMALNA-AAT  [FP-MTFC128GAPALNA-AAT_TBGA100-MFG]  (parts A,B of 2)
U17  SN74LVC1G14QDCKRQ1  [DCK0005A_N]  (parts A,B of 2)
U18  TXU0104BQAR  [BQA0014A-MFG]

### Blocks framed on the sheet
SOC BOOT MODE: C51 C555-C557 J10 R46-R48 R63 R64 R67 R68 R70 R71 U17 U18
QSPI SOC Interface: C35 C36 C38 R16 R18 R23 R25 R26 U7 U12
eMMC SOC Interface: C526 C533 C534 C544 R29 R505 R520 U12 U15

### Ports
Soc_PORz (in), SPI0_CLK (out), SPI0_D0 (out)

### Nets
3V3: C35.1 C36.1 C38.1 C533.1 C534.1 C544.1 C555.1 C556.1 C557.2 R23.2 R25.2 R26.2 R29.2 R47.2 R63.2 R67.2 R70.2 R505.2 U7.8(VCC) U15.F2(VCC) U15.F3(VCC) U15.F4(VCC) U15.F5(VCC) U15.F6(VCC) U15.F7(VCC) U15.F8(VCC) U15.F9(VCC) U15.H3(VCCQ) U15.H8(VCCQ) U15.L2(VCCQ) U15.L4(VCCQ) U15.L7(VCCQ) U15.L9(VCCQ) U15.P3(VCCQ) U15.P8(VCCQ) U17.5(VCC) U18.1(VCCA) U18.14(VCCB)  [project net VDDS33]
GND: C35.2 C36.2 C38.2 C51.2 C526.2 C533.2 C534.2 C544.2 C555.2 C556.2 C557.1 R18.1 R48.1 R64.1 R68.1 R71.1 U7.4(VSS) U7.9(EP) U15.G2(VSS) U15.G3(VSS) U15.G4(VSS) U15.G5(VSS) U15.G6(VSS) U15.G7(VSS) U15.G8(VSS) U15.G9(VSS) U15.H2(VSSQ) U15.H9(VSSQ) U15.J5(VSS) U15.L3(VSSQ) U15.L8(VSSQ) U15.M4(VSSQ) U15.M7(VSSQ) U15.P2(VSSQ) U15.P9(VSSQ) U17.3(GND) U18.7(GND) U18.15(Thermal_Pad)
SOC_MMC0_CD: U12.A5(MMC0_CD)
SOC_MMC0_CLK: R520.1 U12.B6(MMC0_CLK)
SOC_MMC0_CMD: U12.A4(MMC0_CMD) U15.P5(CMD)
SOC_MMC0_D0: U12.B5(MMC0_D0) U15.K2(DAT0)
SOC_MMC0_D1: U12.B4(MMC0_D1) U15.N2(DAT1)
SOC_MMC0_D2: U12.A3(MMC0_D2) U15.K3(DAT2)
SOC_MMC0_D3: U12.A2(MMC0_D3) U15.N3(DAT3)
SOC_MMC0_WP: R29.1 U12.C6(MMC0_WP)
Soc_PORz: R46.2 ; port Soc_PORz
SOC_QSPI0_CLK: R16.1 U12.N2(QSPI0_CLK)
SOC_QSPI0_CS0: R26.1 U7.1(~{CS}) U12.P1(~{QSPI0_CS0})
SOC_QSPI0_D0: U7.5(SI/IO0) U12.N1(QSPI0_D0) U18.13(B1Y)
SOC_QSPI0_D1: U7.2(SO/IO1) U12.N4(QSPI0_D1) U18.12(B2Y)
SOC_QSPI0_D2: R23.1 U7.3(~{WP}/IO2) U12.M4(QSPI0_D2)
SOC_QSPI0_D3: R25.1 U7.7(~{HOLD}/IO3) U12.P3(QSPI0_D3)
SOP0: J10.1 R70.1 U18.2(A1)
SOP1: J10.3 R67.1 U18.3(A2)
SOP2: J10.5 R63.1 U18.4(A3)
SOP3: J10.7 R47.1 U18.5(A4)
SPI0_CLK: U18.11(B3Y) ; port SPI0_CLK
SPI0_D0: U18.10(B4Y) ; port SPI0_D0
NetC51_1: C51.1 R46.1 U17.2(A)
NetC526_1: C526.1 U15.E4(VDDIM)
NetJ10_2: J10.2 R71.2
NetJ10_4: J10.4 R68.2
NetJ10_6: J10.6 R64.2
NetJ10_8: J10.8 R48.2
NetR16_2: R16.2 R18.2 U7.6(SCK)
NetR505_1: R505.1 U15.M5(~{RST})
NetR520_2: R520.2 U15.P6(CLK)
NetU17_4: U17.4(Y) U18.8(OE)

Not connected (* = marked no-connect by the designer): U12 R3(~{QSPI0_CS1})*; U15 A1(NC)* A2(NC)* A9(NC)* A10(NC)* B1(NC)* B10(NC)* D2(VSF1)* D3(VSF2)* D4(VSF3)* D5(VSF4)* D6(VSF5)* D7(VSF6)* D8(VSF7)* D9(VSF8)* E2(Reserved)* E3(Reserved)* E5(Reserved)* E6(Reserved)* E7(Reserved)* E8(Reserved)* E9(Reserved)* H4(Reserved)* H5(Reserved)* H6(Reserved)* H7(Reserved)* J2(Reserved)* J3(Reserved)* J4(Reserved)* J6(Reserved)* J7(Reserved)* J8(Reserved)* J9(Reserved)* K4(Reserved)* K5(DS)* K6(Reserved)* K7(Reserved)* K8(DAT5)* K9(DAT7)* L5(Reserved)* L6(Reserved)* M2(Reserved)* M3(Reserved)* M6(Reserved)* M8(Reserved)* M9(Reserved)* N4(Reserved)* N5(Reserved)* N6(Reserved)* N7(Reserved)* N8(DAT4)* N9(DAT6)* P4(Reserved)* P7(Reserved)* T1(NC)* T10(NC)* U1(NC)* U2(NC)* U9(NC)* U10(NC)*; U17 1(NC)*; U18 6(NC)* 9(NC)*

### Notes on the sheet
- PORz RC Delay:
  - Creates GND to 3.0V delay of 1ms
  - Designed to leave Soc_PORz (after RC filtering) low such that U18 drives SOP[3:0] state for >tSOP.hold time after PORz de-assertion

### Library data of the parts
C35 C36 C533 C534 = CMP-0086059-1: CAP, CERM, 0.1 µF, 10 V,+/- 10%, X5R, 0201; Manufacturer: MuRata; AEC Category: Q200; Cap_F: 100nF; Value: 0.1uF; SizeY_mm: 0.3; AEC Qualified: N; SizeAreaWB_mm2: 2.08; Cap_Case: 0201; SizeArea_mm2: 0.18; SizeZ_mm: 0.33; SizeX_mm: 0.6; TaMax_C: 85°C; TaMin_C: -55°C; U/M: EA
C38 C544 = CMP-0007022-5: CAP, CERM, 4.7 uF, 35 V, +/- 10%, X5R, 0603; Manufacturer: TDK; TaMin_C: -55°C; ESR_ohm: 3.728m; Polarized: N; SizeAreaWB_mm2: 4.68; Value1: 0.003728 ohm; U/M: EA; Value: 4.7uF; TaMax_C: 85°C; SizeZ_mm: 1; SizeX_mm: 1.6; SizeY_mm: 0.8; SizeArea_mm2: 1.28; Cap_F: 4.7µF; IRMS_A: 2.6936A; AEC Category: Q200
C51 = CMP-0078295-1: CAP, CERM, 22 µF, 6.3 V,+/- 20%, X5R, 0603; Manufacturer: MuRata; TaMin_C: -55°C; Polarized: N; SizeAreaWB_mm2: 4.68; U/M: EA; Value: 22uF; TaMax_C: 85°C; SizeZ_mm: 1; SizeX_mm: 1.6; SizeY_mm: 0.8; SizeArea_mm2: 1.28; AEC Category: Q200
C526 = CMP-0079607-1: CAP, CERM, 1 µF, 16 V,+/- 10%, X7R, AEC-Q200 Grade 1, 0603; Manufacturer: TDK; TaMin_C: -55°C; Polarized: N; SizeAreaWB_mm2: 4.68; U/M: EA; Value: 1uF; TaMax_C: 125°C; SizeZ_mm: 1; SizeX_mm: 1.6; SizeY_mm: 0.8; SizeArea_mm2: 1.28; AEC Qualified: Y; AEC Category: Q200
C555-C557 = CMP-0078241-1: as C69 on sheet DLP096D_DMD_Power
J10 = CMP-0075593-2: Header, 2.54mm, 4x2, Gold, SMT; Manufacturer: Samtec; Pitch_mm: 2.54; Gender: Male; Cert_CSA: Y; Green_REACh: Passed; Current_A: 4.9A; Voltage_V: 475V; Shrouded: N; Green_Lifecycle: Active; Row_Count: 2
R16 R520 = CMP-0027002-2: RES, 0, 5%, 0.063 W, 0402; Manufacturer: Rohm; Power_W: 63mW; TempCo: 500 ppm/C; Value_Code: 0000; U/M: EA; Value: 0; EIA_Code: E24; SizeX_mm: 1; SizeY_mm: 0.5; SizeZ_mm: 0.6; Value2: 0.063W; VDC_V: 50V; AEC Category: Q200
R18 R23 R25 R26 R29 R47 R63 R67 R70 R505 = CMP-0027019-1: as R65 on sheet DLP096D_DMD_Interface
R46 = CMP-0022707-2: RES, 49.9, 1%, 0.1 W, AEC-Q200 Grade 0, 0603; Manufacturer: Panasonic; Power_W: 100mW; Value_Code: 49R9; U/M: EA; Value: 49.9; EIA_Code: E96; TempCo: 100 ppm/C; SizeX_mm: 1.6; SizeY_mm: 0.8; SizeZ_mm: 1; Value2: 0.1W; SizeArea_mm2: 1.28; AEC Qualified: Y; AEC Grade: 0; AEC Category: Q200
R48 R64 R68 R71 = CMP-0078193-1: as R37 on sheet DLP096D_DMD_Power
U7 = CMP-0093537-1: FLASH - NOR Memory IC 128Mb (16M x 8) SPI - Quad I/O 133 MHz 8-WSON (6x8); Manufacturer: Cypress Semiconductor; Nominal Supply Current: 16-100mA; AEC Qualified: Yes; Max Supply Voltage: 3.6V; Access Time: 8ns; TaMin_C: -40°C; SizeZ_mm: 0.8mm; TaMax_C: +105°C; Standoff Height: 0mm; Memory Size: 128Mbits; Min Supply Voltage: 1.65V; Frequency_Fixed: 133MHz
U12 = CMP-0093674-1: as U12 on sheet DLP096D_DMD_Interface
U15 = CMP-0088841-1: e.MMC Memory, 8GB NOR FLASH memory; Manufacturer: Micron; Frequency_Fixed: 200MHz; TaMax_C: +105°C; Standoff Height: 0.316mm; AEC Grade: Grade 2; TaMin_C: -40°C; AEC Qualified: Yes; Nominal Supply Current: 90-150mA; Interface: Other; Memory Size: 8GBytes; SizeZ_mm: 1.2mm; Max Supply Voltage: 3.6V; Min Supply Voltage: 1.7V; Memory Type: FLASH,NAND
U17 = CMP-0082079-1: Automotive Single Schmitt-Trigger Inverter, DCK0005A (SOT-SC70-5); Alternate Manufacturer: Texas Instruments; SizeAreaWB_mm2: 9.3; SizeZ_mm: 1.1; SizeX_mm: 2.1; SizeY_mm: 2; SizeArea_mm2: 4.2; CompType: IC; AEC Qualified: Y; AEC Category: Q200
U18 = CMP-0095233-1: Four channel unidirectional level shifter 14-WQFN -40 to 125; Manufacturer: Texas Instruments; V B Min: 1.08V; TaMin_C: -40°C; AEC Qualified: No; TaMax_C: +125°C; Propagation Delay: 8ns; Data Rate: 200Mbits/s; Standoff Height: 0mm; TJmax_C: +150°C; SizeZ_mm: 0.8mm; PositionCount: 1; V A Max: 5.5V; Number Of Inputs: 4; Nominal Supply Current: 2.5uA

## Sheet DLP096D_Interfaces_Sockets.SchDoc: Interfaces_Sockets
size 431 x 279 mm; Date: Not shown in title block; ApprovedBy: Not shown in title block; CheckedBy: Not shown in title block; Author: Not shown in title block; CompanyName: Not shown in title block; DrawnBy: A. Whitehead; Engineer: Not shown in title block; Organization: Not shown in title block; Address1: Not shown in title block; Address2: Not shown in title block; Address3: Not shown in title block; Address4: Not shown in title block; DocumentNumber: 8; Revision: Use project parameter SCH_Rev; SheetNumber: 8; SheetTotal: 10; PageSetup: Record=PageOptions¦CenterHorizontal=True¦CenterVertical=True¦PrintScale=1.00¦XCorrection=1.00¦YCorrection=1.00¦PrintKind=0¦BorderSize=5000000¦LeftOffset=0¦BottomOffset=0¦Orientation=2¦PaperLength=1000¦PaperWidth=1000¦Scale=100¦PaperSource=15¦PrintQuality=600¦MediaType=1¦DitherType=10¦PaperKind=Letter¦PrintScaleMode=1
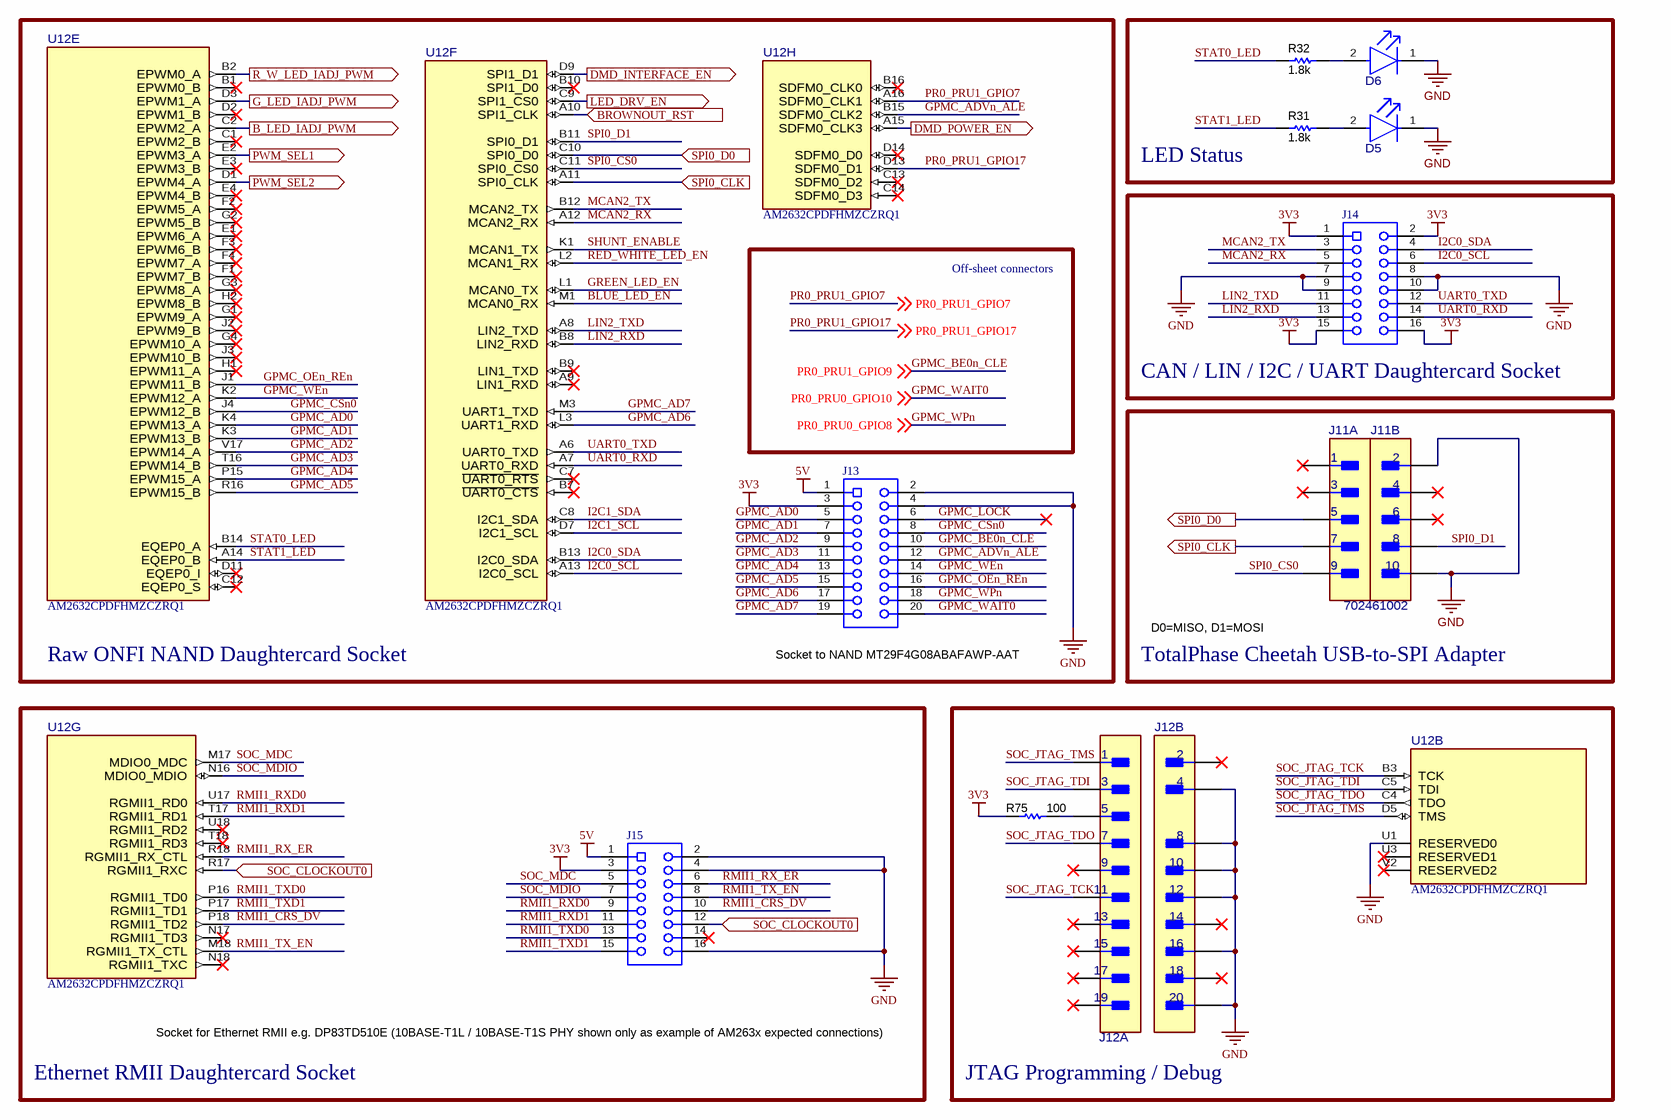
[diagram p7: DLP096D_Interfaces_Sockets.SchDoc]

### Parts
D5  LSL29K-G1H2-1-Z  [FP-LSL29K-G1H2-1-Z_0603-0]  (value not drawn)
D6  LSL29K-G1H2-1-Z  [FP-LSL29K-G1H2-1-Z_0603-0]  (value not drawn)
J11  702461002  [FP-702461002_HDR10-MFG]  (value not drawn)  (parts A,B of 2)
J12  FTR-110-03-G-D-06  [FP-FTR-110-03-G-D-06_HDR19-MFG]  (value not drawn)  (parts A,B of 2)
J13  RSM-110-02-L-D  [Samtec_RSM-110-02-x-D]  (value not drawn)
J14  FLE-108-01-G-DV-A  [Samtec_FLE-108-01-x-DV-A]  (value not drawn)
J15  FLE-108-01-G-DV-A  [Samtec_FLE-108-01-x-DV-A]  (value not drawn)
R31  ValueDisplayed: 1.8k  [0402L]  (hidden comment: CRCW04021K80JNED)
R32  ValueDisplayed: 1.8k  [0402L]  (hidden comment: CRCW04021K80JNED)
R75  ValueDisplayed: 100  [0402L]  (hidden comment: ERJ-2GEJ101X)
U12  PartNumber: AM2632CPDFHMZCZRQ1  [ZCZ0324A-MFG]  (hidden comment: XAM2634AOLFGMZCZQ)  (parts B,E,F,G,H of 13)

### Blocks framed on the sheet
Raw ONFI NAND Daughtercard Socket: J13 U12
LED Status: D5 D6 R31 R32
CAN / LIN / I2C / UART Daughtercard Socket: J14
TotalPhase Cheetah USB-to-SPI Adapter: J11
Ethernet RMII Daughtercard Socket: J15 U12
JTAG Programming / Debug: J12 R75 U12

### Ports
B_LED_IADJ_PWM (out), BROWNOUT_RST (in), DMD_INTERFACE_EN (out), DMD_POWER_EN (out), G_LED_IADJ_PWM (out), LED_DRV_EN (out), PWM_SEL1 (out), PWM_SEL2 (out), R_W_LED_IADJ_PWM (out), SOC_CLOCKOUT0 (in), SPI0_CLK (in), SPI0_CLK (out), SPI0_D0 (in), SPI0_D0 (out)

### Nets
3V3: J13.3 J14.1 J14.2 J14.15 J14.16 J15.3 R75.1  [project net VDDS33]
5V: J13.1 J15.1
GND: D5.1(CATHODE) D6.1(CATHODE) J11.2 J11.10 J12.4 J12.8 J12.10 J12.12 J12.16 J12.20 J13.2 J13.4 J14.7 J14.8 J14.9 J14.10 J15.2 J15.4 J15.16 U12.U1(RESERVED0)
B_LED_IADJ_PWM: U12.C2(EPWM2_A) ; port B_LED_IADJ_PWM
BLUE_LED_EN: U12.M1(MCAN0_RX)
BROWNOUT_RST: U12.A10(SPI1_CLK) ; port BROWNOUT_RST
DMD_INTERFACE_EN: U12.D9(SPI1_D1) ; port DMD_INTERFACE_EN
DMD_POWER_EN: U12.A15(SDFM0_CLK3) ; port DMD_POWER_EN
G_LED_IADJ_PWM: U12.D3(EPWM1_A) ; port G_LED_IADJ_PWM
GPMC_AD0: J13.5 U12.K4(EPWM13_A)
GPMC_AD1: J13.7 U12.K3(EPWM13_B)
GPMC_AD2: J13.9 U12.V17(EPWM14_A)
GPMC_AD3: J13.11 U12.T16(EPWM14_B)
GPMC_AD4: J13.13 U12.P15(EPWM15_A)
GPMC_AD5: J13.15 U12.R16(EPWM15_B)
GPMC_AD6: J13.17 U12.L3(UART1_RXD)
GPMC_AD7: J13.19 U12.M3(UART1_TXD)
GPMC_ADVn_ALE: J13.12 U12.B15(SDFM0_CLK2)
GPMC_BE0n_CLE: J13.10 ; off-sheet PR0_PRU1_GPIO9  [also labelled PR0_PRU1_GPIO9]
GPMC_CSn0: J13.8 U12.J4(EPWM12_B)
GPMC_LOCK: J13.6
GPMC_OEn_REn: J13.16 U12.J1(EPWM11_B)
GPMC_WAIT0: J13.20 ; off-sheet PR0_PRU0_GPIO10  [also labelled PR0_PRU0_GPIO10]
GPMC_WEn: J13.14 U12.K2(EPWM12_A)
GPMC_WPn: J13.18 ; off-sheet PR0_PRU0_GPIO8  [also labelled PR0_PRU0_GPIO8]
GREEN_LED_EN: U12.L1(MCAN0_TX)
I2C0_SCL: J14.6 U12.A13(I2C0_SCL)
I2C0_SDA: J14.4 U12.B13(I2C0_SDA)
I2C1_SCL: U12.D7(I2C1_SCL)
I2C1_SDA: U12.C8(I2C1_SDA)
LED_DRV_EN: U12.C9(SPI1_CS0) ; port LED_DRV_EN
LIN2_RXD: J14.13 U12.B8(LIN2_RXD)
LIN2_TXD: J14.11 U12.A8(LIN2_TXD)
MCAN2_RX: J14.5 U12.A12(MCAN2_RX)
MCAN2_TX: J14.3 U12.B12(MCAN2_TX)
PR0_PRU1_GPIO7: U12.A16(SDFM0_CLK1) ; off-sheet PR0_PRU1_GPIO7  [project net DMD_D7]
PR0_PRU1_GPIO17: U12.D13(SDFM0_D1) ; off-sheet PR0_PRU1_GPIO17  [project net DMD_SAC_CLK]
PWM_SEL1: U12.E2(EPWM3_A) ; port PWM_SEL1
PWM_SEL2: U12.D1(EPWM4_A) ; port PWM_SEL2
R_W_LED_IADJ_PWM: U12.B2(EPWM0_A) ; port R_W_LED_IADJ_PWM
RED_WHITE_LED_EN: U12.L2(MCAN1_RX)
RMII1_CRS_DV: J15.10 U12.P18(RGMII1_TD2)
RMII1_RX_ER: J15.6 U12.R18(RGMII1_RX_CTL)
RMII1_RXD0: J15.9 U12.U17(RGMII1_RD0)
RMII1_RXD1: J15.11 U12.T17(RGMII1_RD1)
RMII1_TX_EN: J15.8 U12.M18(RGMII1_TX_CTL)
RMII1_TXD0: J15.13 U12.P16(RGMII1_TD0)
RMII1_TXD1: J15.15 U12.P17(RGMII1_TD1)
SHUNT_ENABLE: U12.K1(MCAN1_TX)
SOC_CLOCKOUT0: J15.12 U12.R17(RGMII1_RXC) ; port SOC_CLOCKOUT0
SOC_JTAG_TCK: J12.11 U12.B3(TCK)
SOC_JTAG_TDI: J12.3 U12.C5(TDI)
SOC_JTAG_TDO: J12.7 U12.C4(TDO)
SOC_JTAG_TMS: J12.1 U12.D5(TMS)
SOC_MDC: J15.5 U12.M17(MDIO0_MDC)
SOC_MDIO: J15.7 U12.N16(MDIO0_MDIO)
SPI0_CLK: J11.7 U12.A11(SPI0_CLK) ; port SPI0_CLK
SPI0_CS0: J11.9 U12.C11(SPI0_CS0)
SPI0_D0: J11.5 U12.C10(SPI0_D0) ; port SPI0_D0
SPI0_D1: J11.8 U12.B11(SPI0_D1)
STAT0_LED: R32.2 U12.B14(EQEP0_A)
STAT1_LED: R31.2 U12.A14(EQEP0_B)
UART0_RXD: J14.14 U12.A7(UART0_RXD)
UART0_TXD: J14.12 U12.A6(UART0_TXD)
NetD5_2: D5.2(ANODE) R31.1
NetD6_2: D6.2(ANODE) R32.1
NetJ12_5: J12.5 R75.2

Not connected (* = marked no-connect by the designer): J11 1* 3* 4* 6*; J12 2* 9* 13* 14* 15* 17* 18* 19*; J15 14*; U12 A9(LIN1_RXD)* B1(EPWM0_B)* B7(~{UART0_CTS})* B9(LIN1_TXD)* B10(SPI1_D0)* B16(SDFM0_CLK0)* C1(EPWM2_B)* C7(~{UART0_RTS})* C12(EQEP0_S)* C13(SDFM0_D2)* C14(SDFM0_D3)* D2(EPWM1_B)* D11(EQEP0_I)* D14(SDFM0_D0)* E1(EPWM6_A)* E3(EPWM3_B)* E4(EPWM4_B)* F1(EPWM7_B)* F2(EPWM5_A)* F3(EPWM6_B)* F4(EPWM7_A)* G1(EPWM9_A)* G2(EPWM5_B)* G3(EPWM8_A)* G4(EPWM10_A)* H1(EPWM11_A)* H2(EPWM8_B)* J2(EPWM9_B)* J3(EPWM10_B)* N17(RGMII1_TD3)* N18(RGMII1_TXC)* T18(RGMII1_RD3)* U3(RESERVED1)* U18(RGMII1_RD2)* V2(RESERVED2)*

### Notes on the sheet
- Off-sheet connectors
- (near J13) Socket to NAND MT29F4G08ABAFAWP-AAT
- D0=MISO, D1=MOSI
- Socket for Ethernet RMII e.g. DP83TD510E (10BASE-T1L / 10BASE-T1S PHY shown only as example of AM263x expected connections)

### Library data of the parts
D5 D6 = CMP-0092845-1: LED Uni-Color Red 643nm 2-Pin Chip 0603(1608Metric) T/R; Manufacturer: OSRAM Opto Semiconductors; AEC Grade: Grade 2; LuminousFlux_PhiV: 8.1/16.1lm; Vf_V: 1.8V; Forward Current: 2mA; Led Orientation: Top View; SizeZ_mm: 0.67mm; AEC Qualified: Yes; Luminous Intensity: 1.8-2.24/3.55-4.5mcd; Vr_V: 12V; Angle: 160°; LambdaD: 630nm; Tjmax_C: 110°C
J11 = CMP-0089821-1: Connector Header Through Hole 10 position 0.100" (2.54mm); Manufacturer: Molex; Voltage_V: 250V; Conn Gender: Male; SizeZ_mm: 9.47mm; Standoff Height: 0.38mm; Row_Count: 2; Conn Orientation: Vertical; AEC Qualified: No; ContactFinish: Gold,Nickel; Current_A: 2.5A
J12 = CMP-0092119-1: Connector Header Surface Mount 20 position 0.050" (1.27mm); Manufacturer: Samtec; ContactFinish: Gold; Standoff Height: 1mm; Row_Count: 2; AEC Qualified: No; Conn Orientation: Vertical; Current_A: 3.1A; Conn Gender: Male; SizeZ_mm: 7.58mm
J13 = CMP-0081743-1: Receptacle, 1.27mm, 10x2, Gold with Tin tail, SMT; Manufacturer: Samtec; Pitch_mm: 1.27; Gender: Female; Cert_UL: Y; Current_A: 3.1A; RowSpacing_mm: 2.54; Row_Count: 2; CompType: Socket Strip
J14 J15 = CMP-0077240-1: Receptacle, 1.27mm, 8x2, Gold, SMT; Manufacturer: Samtec; Pitch_mm: 1.27; Gender: Female; Cert_CSA: Y; Current_A: 2A; CT: True; Row_Count: 2; CompType: Socket Strip; CNHeader: False
R31 R32 = CMP-0026858-5: RES, 1.8 k, 5%, 0.063 W, AEC-Q200 Grade 0, 0402; Manufacturer: Vishay-Dale; Power_W: 63mW; TempCo: 200 ppm/C; Value_Code: 1k80; Value: 1.8k; EIA_Code: E24; SizeX_mm: 1; SizeY_mm: 0.5; SizeZ_mm: 0.6; Value2: 0.063W; AEC Qualified: Y; VDC_V: 50V; AEC Category: Q200; AEC Grade: 0
R75 = CMP-0026993-2: RES, 100, 5%, 0.1 W, AEC-Q200 Grade 0, 0402; Manufacturer: Panasonic; Power_W: 100mW; TempCo: 200 ppm/C; Value_Code: 100R; U/M: EA; Value: 100; EIA_Code: E24; SizeX_mm: 1; SizeY_mm: 0.5; SizeZ_mm: 0.6; Value2: 0.1W; AEC Qualified: Y; AEC Grade: 0; AEC Category: Q200
U12 = CMP-0093674-1: as U12 on sheet DLP096D_DMD_Interface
